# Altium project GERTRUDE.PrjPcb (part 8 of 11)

## Sheet HEADERS_JMEDIA_JMISC.SchDoc: JMEDIA JMISC
size A3; SheetNumber: 21; SheetTotal: 51
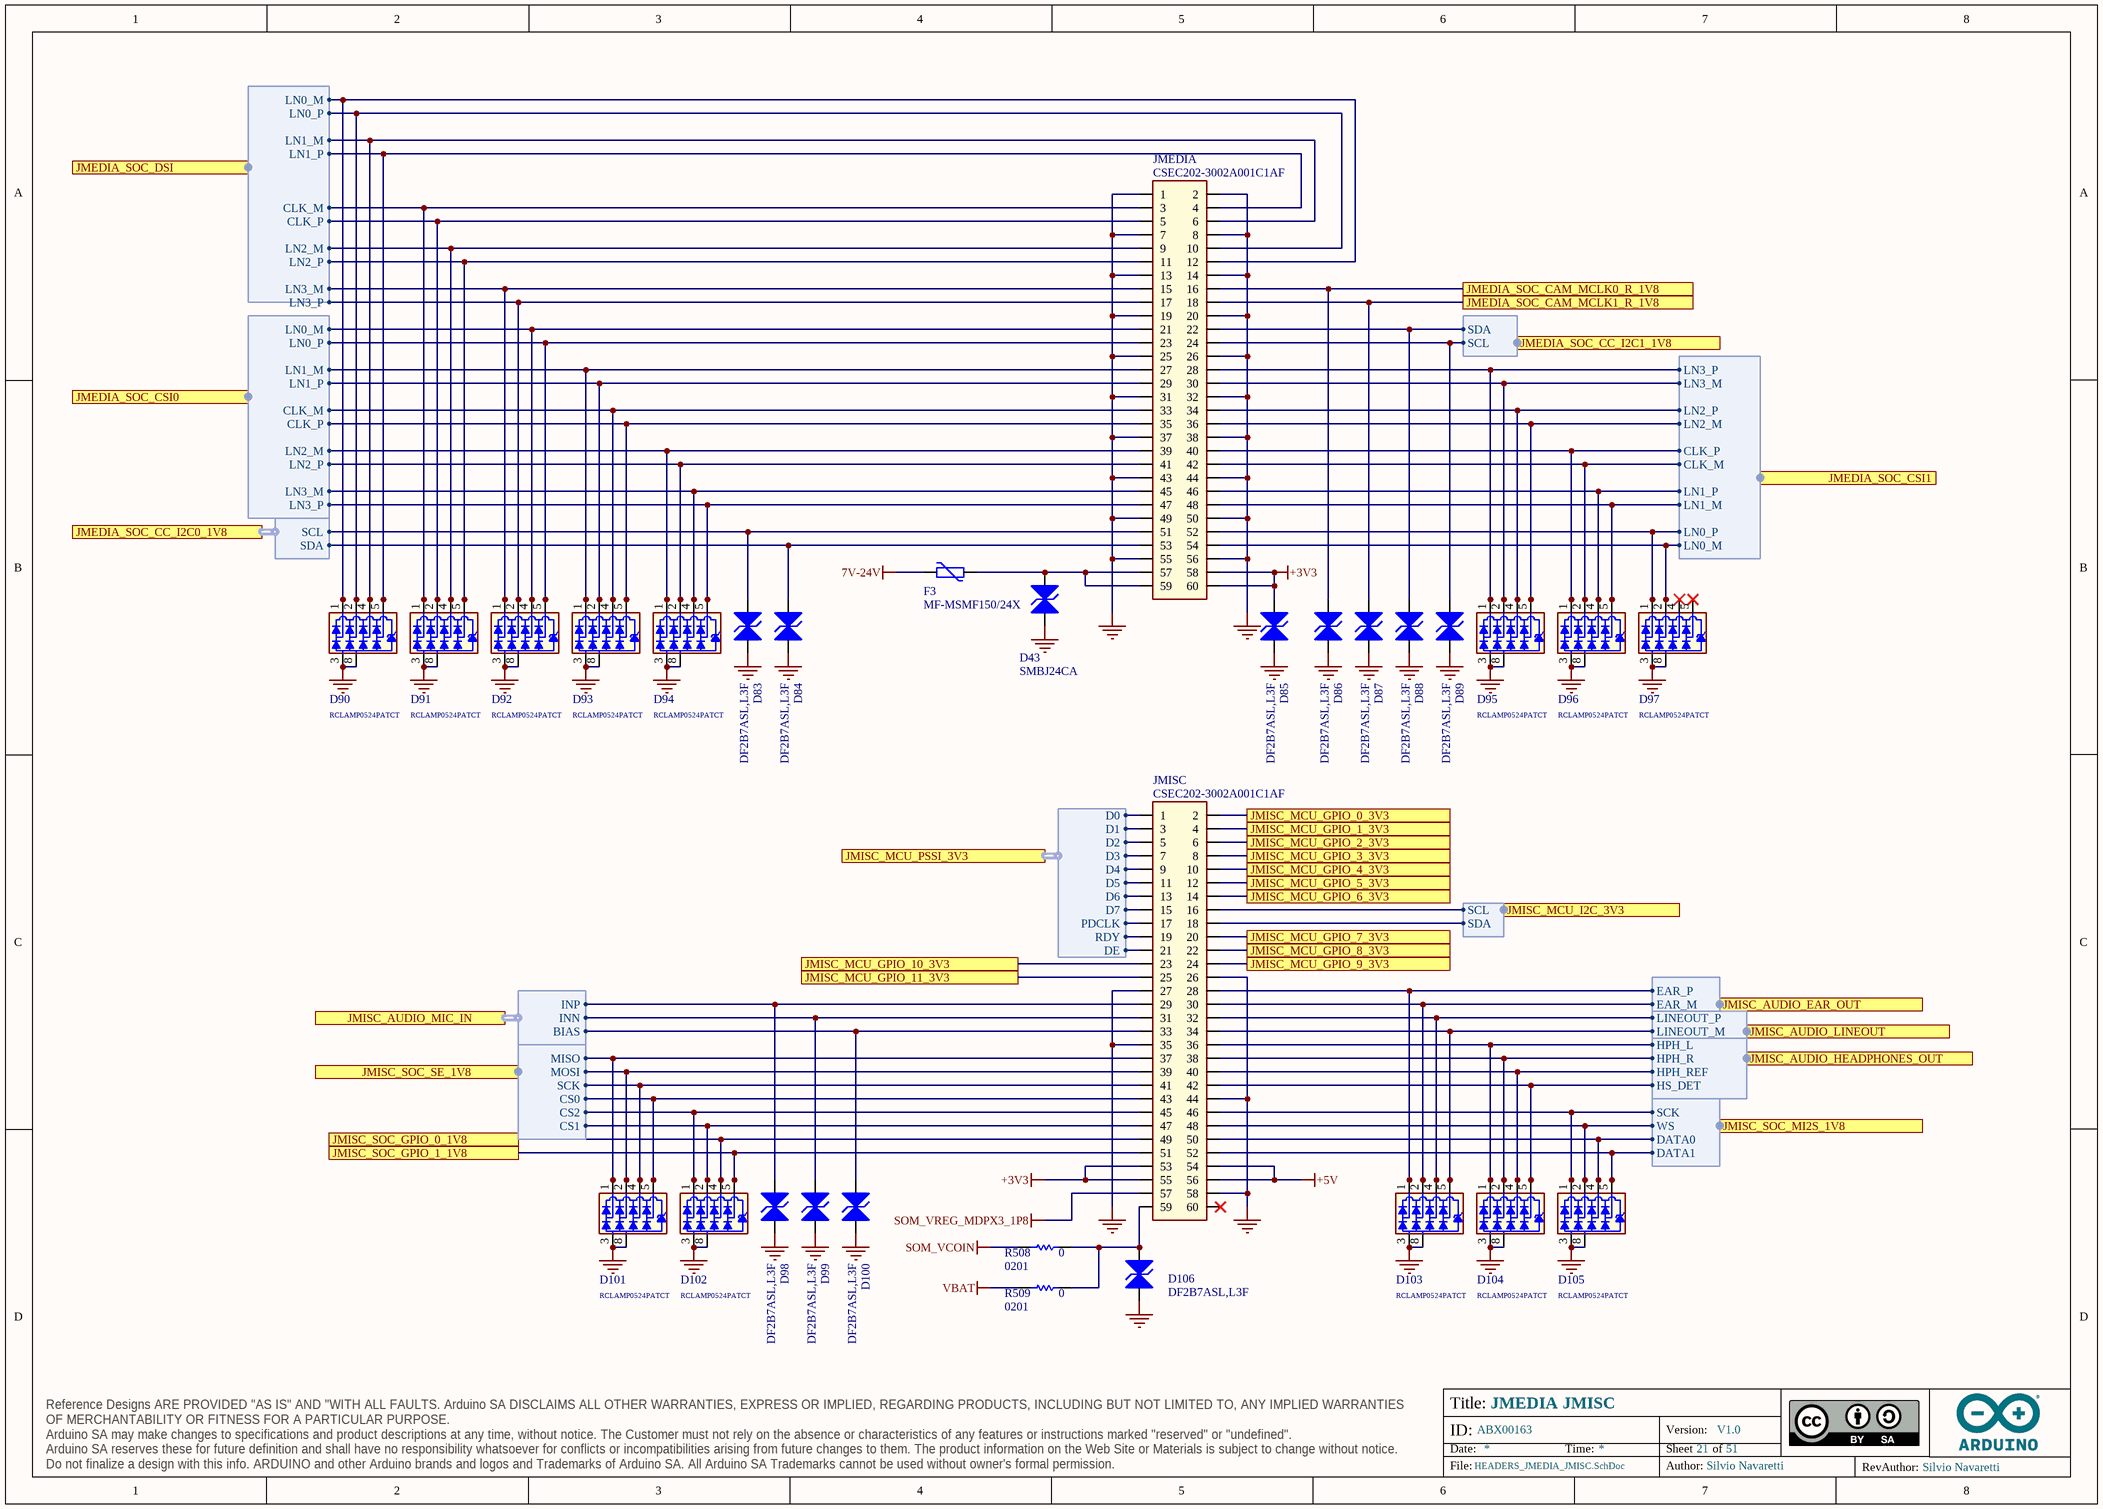
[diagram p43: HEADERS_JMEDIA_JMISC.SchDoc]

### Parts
D43  SMBJ24CA  [SMB_NOPOLARITY]
D83  DF2B7ASL,L3F  [DF2B7ASL,L3F]
D84  DF2B7ASL,L3F  [DF2B7ASL,L3F]
D85  DF2B7ASL,L3F  [DF2B7ASL,L3F]
D86  DF2B7ASL,L3F  [DF2B7ASL,L3F]
D87  DF2B7ASL,L3F  [DF2B7ASL,L3F]
D88  DF2B7ASL,L3F  [DF2B7ASL,L3F]
D89  DF2B7ASL,L3F  [DF2B7ASL,L3F]
D90  RCLAMP0524PATCT  [SLP2510P8]
D91  RCLAMP0524PATCT  [SLP2510P8]
D92  RCLAMP0524PATCT  [SLP2510P8]
D93  RCLAMP0524PATCT  [SLP2510P8]
D94  RCLAMP0524PATCT  [SLP2510P8]
D95  RCLAMP0524PATCT  [SLP2510P8]
D96  RCLAMP0524PATCT  [SLP2510P8]
D97  RCLAMP0524PATCT  [SLP2510P8]
D98  DF2B7ASL,L3F  [DF2B7ASL,L3F]
D99  DF2B7ASL,L3F  [DF2B7ASL,L3F]
D100  DF2B7ASL,L3F  [DF2B7ASL,L3F]
D101  RCLAMP0524PATCT  [SLP2510P8]
D102  RCLAMP0524PATCT  [SLP2510P8]
D103  RCLAMP0524PATCT  [SLP2510P8]
D104  RCLAMP0524PATCT  [SLP2510P8]
D105  RCLAMP0524PATCT  [SLP2510P8]
D106  DF2B7ASL,L3F  [DF2B7ASL,L3F]
F3  MF-MSMF150/24X  [1812]
JMEDIA  CSEC202-3002A001C1AF  [CSEC202-3002A001C1AF]
JMISC  CSEC202-3002A001C1AF  [CSEC202-3002A001C1AF]
R508  value 0  Case Code (Imperial): 0201  [RES-0201]  (hidden comment: CRCW02010000Z0ED)
R509  value 0  Case Code (Imperial): 0201  [RES-0201]  (hidden comment: CRCW02010000Z0ED)

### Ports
JMEDIA_SOC_CAM_MCLK0_R_1V8, JMEDIA_SOC_CAM_MCLK1_R_1V8, JMEDIA_SOC_CC_I2C0_1V8 (harness I2C), JMEDIA_SOC_CC_I2C1_1V8 (harness I2C), JMEDIA_SOC_CSI0 (harness MIPI_4LANES), JMEDIA_SOC_CSI1 (harness MIPI_4LANES), JMEDIA_SOC_DSI (harness MIPI_4LANES), JMISC_AUDIO_EAR_OUT (harness EAT), JMISC_AUDIO_HEADPHONES_OUT (harness HEADPHONES), JMISC_AUDIO_LINEOUT (harness LINEOUT), JMISC_AUDIO_MIC_IN (harness MIC), JMISC_MCU_GPIO_0_3V3, JMISC_MCU_GPIO_1_3V3, JMISC_MCU_GPIO_2_3V3, JMISC_MCU_GPIO_3_3V3, JMISC_MCU_GPIO_4_3V3, JMISC_MCU_GPIO_5_3V3, JMISC_MCU_GPIO_6_3V3, JMISC_MCU_GPIO_7_3V3, JMISC_MCU_GPIO_8_3V3, JMISC_MCU_GPIO_9_3V3, JMISC_MCU_GPIO_10_3V3, JMISC_MCU_GPIO_11_3V3, JMISC_MCU_I2C_3V3 (harness I2C), JMISC_MCU_PSSI_3V3 (harness PSSI), JMISC_SOC_GPIO_0_1V8, JMISC_SOC_GPIO_1_1V8, JMISC_SOC_MI2S_1V8 (harness SOM_MD_I2S), JMISC_SOC_SE_1V8 (harness SOM_MD_SPI_3CS)

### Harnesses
MIPI_4LANES: LN3_M, LN2_M, LN2_P, LN0_M, LN0_P, CLK_M, CLK_P, LN1_M, LN1_P, LN3_P
I2C: SDA, SCL
EAT: EAR_P, EAR_M
MIC: INP, INN, BIAS
LINEOUT: LINEOUT_P, LINEOUT_M
HEADPHONES: HPH_L, HPH_R, HPH_REF, HS_DET
SOM_MD_SPI_3CS: SCK, MISO, MOSI, CS0, CS1, CS2
SOM_MD_I2S: SCK, WS, DATA0, DATA1
PSSI: D0, D1, D2, D3, D4, D5, D6, D7, PDCLK, RDY, DE

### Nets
7V-24V: F3.1
+3V3: D85.2(A2) JMEDIA.58 JMEDIA.60 JMISC.53 JMISC.55
+5V: JMISC.54 JMISC.56
GND: D43.1(A1) D83.1(A1) D84.1(A1) D85.1(A1) D86.1(A1) D87.1(A1) D88.1(A1) D89.1(A1) D90.3 D90.8 D91.3 D91.8 D92.3 D92.8 D93.3 D93.8 D94.3 D94.8 D95.3 D95.8 D96.3 D96.8 D97.3 D97.8 D98.1(A1) D99.1(A1) D100.1(A1) D101.3 D101.8 D102.3 D102.8 D103.3 D103.8 D104.3 D104.8 D105.3 D105.8 D106.1(A1) JMEDIA.1 JMEDIA.2 JMEDIA.7 JMEDIA.8 JMEDIA.13 JMEDIA.14 JMEDIA.19 JMEDIA.20 JMEDIA.25 JMEDIA.26 JMEDIA.31 JMEDIA.32 JMEDIA.37 JMEDIA.38 JMEDIA.43 JMEDIA.44 JMEDIA.49 JMEDIA.50 JMEDIA.55 JMEDIA.56 JMISC.26 JMISC.27 JMISC.35 JMISC.44 JMISC.58
SOM_VCOIN: R508.2
SOM_VREG_MDPX3_1P8: JMISC.57
VBAT: R509.2
A_CLK_N: D91.1 D91.10 JMEDIA.3 ; port JMEDIA_SOC_DSI.CLK_M
A_CLK_N: D93.4 D93.7 JMEDIA.33 ; port JMEDIA_SOC_CSI0.CLK_M  [a separate net that carries the same name]
A_CLK_N: D96.2 D96.9 JMEDIA.42 ; port JMEDIA_SOC_CSI1.CLK_M  [a separate net that carries the same name]
A_CLK_P: D91.2 D91.9 JMEDIA.5 ; port JMEDIA_SOC_DSI.CLK_P
A_CLK_P: D93.5 D93.6 JMEDIA.35 ; port JMEDIA_SOC_CSI0.CLK_P  [a separate net that carries the same name]
A_CLK_P: D96.1 D96.10 JMEDIA.40 ; port JMEDIA_SOC_CSI1.CLK_P  [a separate net that carries the same name]
A_LN0_N: D90.1 D90.10 JMEDIA.12 ; port JMEDIA_SOC_DSI.LN0_M
A_LN0_N: D92.4 D92.7 JMEDIA.21 ; port JMEDIA_SOC_CSI0.LN0_M  [a separate net that carries the same name]
A_LN0_N: D97.2 D97.9 JMEDIA.54 ; port JMEDIA_SOC_CSI1.LN0_M  [a separate net that carries the same name]
A_LN0_P: D90.2 D90.9 JMEDIA.10 ; port JMEDIA_SOC_DSI.LN0_P
A_LN0_P: D92.5 D92.6 JMEDIA.23 ; port JMEDIA_SOC_CSI0.LN0_P  [a separate net that carries the same name]
A_LN0_P: D97.1 D97.10 JMEDIA.52 ; port JMEDIA_SOC_CSI1.LN0_P  [a separate net that carries the same name]
A_LN1_N: D90.4 D90.7 JMEDIA.6 ; port JMEDIA_SOC_DSI.LN1_M
A_LN1_N: D93.1 D93.10 JMEDIA.27 ; port JMEDIA_SOC_CSI0.LN1_M  [a separate net that carries the same name]
A_LN1_N: D96.5 D96.6 JMEDIA.48 ; port JMEDIA_SOC_CSI1.LN1_M  [a separate net that carries the same name]
A_LN1_P: D90.5 D90.6 JMEDIA.4 ; port JMEDIA_SOC_DSI.LN1_P
A_LN1_P: D93.2 D93.9 JMEDIA.29 ; port JMEDIA_SOC_CSI0.LN1_P  [a separate net that carries the same name]
A_LN1_P: D96.4 D96.7 JMEDIA.46 ; port JMEDIA_SOC_CSI1.LN1_P  [a separate net that carries the same name]
A_LN2_N: D91.4 D91.7 JMEDIA.9 ; port JMEDIA_SOC_DSI.LN2_M
A_LN2_N: D94.1 D94.10 JMEDIA.39 ; port JMEDIA_SOC_CSI0.LN2_M  [a separate net that carries the same name]
A_LN2_N: D95.5 D95.6 JMEDIA.36 ; port JMEDIA_SOC_CSI1.LN2_M  [a separate net that carries the same name]
A_LN2_P: D91.5 D91.6 JMEDIA.11 ; port JMEDIA_SOC_DSI.LN2_P
A_LN2_P: D94.2 D94.9 JMEDIA.41 ; port JMEDIA_SOC_CSI0.LN2_P  [a separate net that carries the same name]
A_LN2_P: D95.4 D95.7 JMEDIA.34 ; port JMEDIA_SOC_CSI1.LN2_P  [a separate net that carries the same name]
A_LN3_N: D92.1 D92.10 JMEDIA.15 ; port JMEDIA_SOC_DSI.LN3_M
A_LN3_N: D94.4 D94.7 JMEDIA.45 ; port JMEDIA_SOC_CSI0.LN3_M  [a separate net that carries the same name]
A_LN3_N: D95.2 D95.9 JMEDIA.30 ; port JMEDIA_SOC_CSI1.LN3_M  [a separate net that carries the same name]
A_LN3_P: D92.2 D92.9 JMEDIA.17 ; port JMEDIA_SOC_DSI.LN3_P
A_LN3_P: D94.5 D94.6 JMEDIA.47 ; port JMEDIA_SOC_CSI0.LN3_P  [a separate net that carries the same name]
A_LN3_P: D95.1 D95.10 JMEDIA.28 ; port JMEDIA_SOC_CSI1.LN3_P  [a separate net that carries the same name]
MD_CCI_I2C0.SCL: D83.2(A2) JMEDIA.51 ; port JMEDIA_SOC_CC_I2C0_1V8.SCL
MD_CCI_I2C0.SDA: D84.2(A2) JMEDIA.53 ; port JMEDIA_SOC_CC_I2C0_1V8.SDA
MD_CCI_I2C2.SCL: D89.2(A2) JMEDIA.24 ; port JMEDIA_SOC_CC_I2C1_1V8.SCL
MD_CCI_I2C2.SDA: D88.2(A2) JMEDIA.22 ; port JMEDIA_SOC_CC_I2C1_1V8.SDA
MD_GPIO_10: D101.1 D101.10 JMISC.37 ; port JMISC_SOC_SE_1V8.MISO
MD_GPIO_11: D101.2 D101.9 JMISC.39 ; port JMISC_SOC_SE_1V8.MOSI
MD_GPIO_12: D101.4 D101.7 JMISC.41 ; port JMISC_SOC_SE_1V8.SCK
MD_GPIO_13: D101.5 D101.6 JMISC.43 ; port JMISC_SOC_SE_1V8.CS0
MD_GPIO_14: D102.2 D102.9 JMISC.47 ; port JMISC_SOC_SE_1V8.CS1
MD_GPIO_15: D102.1 D102.10 JMISC.45 ; port JMISC_SOC_SE_1V8.CS2
MD_GPIO_67: D86.2(A2) JMEDIA.16 ; port JMEDIA_SOC_CAM_MCLK0_R_1V8
MD_GPIO_68: D87.2(A2) JMEDIA.18 ; port JMEDIA_SOC_CAM_MCLK1_R_1V8
MD_GPIO_73: D102.4 D102.7 JMISC.49 ; port JMISC_SOC_GPIO_0_1V8
MD_GPIO_74: D102.5 D102.6 JMISC.51 ; port JMISC_SOC_GPIO_1_1V8
MD_LPASS_GPIO_120: D105.1 D105.10 JMISC.46 ; port JMISC_SOC_MI2S_1V8.SCK
MD_LPASS_GPIO_121: D105.2 D105.9 JMISC.48 ; port JMISC_SOC_MI2S_1V8.WS
MD_LPASS_GPIO_122: D105.4 D105.7 JMISC.50 ; port JMISC_SOC_MI2S_1V8.DATA0
MD_LPASS_GPIO_123: D105.5 D105.6 JMISC.52 ; port JMISC_SOC_MI2S_1V8.DATA1
MIC_IN5_IN6.BIAS: D100.2(A2) JMISC.33 ; port JMISC_AUDIO_MIC_IN.BIAS
PA0: JMISC.20 ; port JMISC_MCU_GPIO_7_3V3
PA1: JMISC.22 ; port JMISC_MCU_GPIO_8_3V3
PA2: JMISC.24 ; port JMISC_MCU_GPIO_9_3V3
PA6: JMISC.17 ; port JMISC_MCU_PSSI_3V3.PDCLK
PA9: JMISC.1 ; port JMISC_MCU_PSSI_3V3.D0
PA11: JMISC.23 ; port JMISC_MCU_GPIO_10_3V3
PA12: JMISC.25 ; port JMISC_MCU_GPIO_11_3V3
PC7: JMISC.3 ; port JMISC_MCU_PSSI_3V3.D1
PC8: JMISC.5 ; port JMISC_MCU_PSSI_3V3.D2
PC11: JMISC.9 ; port JMISC_MCU_PSSI_3V3.D4
PD3: JMISC.11 ; port JMISC_MCU_PSSI_3V3.D5
PE1: JMISC.7 ; port JMISC_MCU_PSSI_3V3.D3
PE2: JMISC.2 ; port JMISC_MCU_GPIO_0_3V3
PE3: JMISC.4 ; port JMISC_MCU_GPIO_1_3V3
PE4: JMISC.6 ; port JMISC_MCU_GPIO_2_3V3
PE5: JMISC.8 ; port JMISC_MCU_GPIO_3_3V3
PE6: JMISC.10 ; port JMISC_MCU_GPIO_4_3V3
PE7: JMISC.12 ; port JMISC_MCU_GPIO_5_3V3
PE8: JMISC.14 ; port JMISC_MCU_GPIO_6_3V3
PF0: JMISC.18 ; port JMISC_MCU_I2C_3V3.SDA
PF1: JMISC.16 ; port JMISC_MCU_I2C_3V3.SCL
PF4: JMISC.13 ; port JMISC_MCU_PSSI_3V3.D6
PH8: JMISC.21 ; port JMISC_MCU_PSSI_3V3.DE
PI5: JMISC.19 ; port JMISC_MCU_PSSI_3V3.RDY
PI7: JMISC.15 ; port JMISC_MCU_PSSI_3V3.D7
NetC209_2: D98.2(A2) JMISC.29 ; port JMISC_AUDIO_MIC_IN.INP
NetC217_2: D99.2(A2) JMISC.31 ; port JMISC_AUDIO_MIC_IN.INN
NetC248_2: D104.1 D104.10 JMISC.36 ; port JMISC_AUDIO_HEADPHONES_OUT.HPH_L
NetC295_2: D104.2 D104.9 JMISC.38 ; port JMISC_AUDIO_HEADPHONES_OUT.HPH_R
NetD43_2: D43.2(A2) F3.2 JMEDIA.57 JMEDIA.59
NetD97_4: D97.4 D97.7
NetD97_5: D97.5 D97.6
NetD103_1: D103.1 D103.10 JMISC.28 ; port JMISC_AUDIO_EAR_OUT.EAR_P
NetD103_2: D103.2 D103.9 JMISC.30 ; port JMISC_AUDIO_EAR_OUT.EAR_M
NetD103_4: D103.4 D103.7 JMISC.32 ; port JMISC_AUDIO_LINEOUT.LINEOUT_P
NetD103_5: D103.5 D103.6 JMISC.34 ; port JMISC_AUDIO_LINEOUT.LINEOUT_M
NetD104_4: D104.4 D104.7 JMISC.40 ; port JMISC_AUDIO_HEADPHONES_OUT.HPH_REF
NetD104_5: D104.5 D104.6 JMISC.42 ; port JMISC_AUDIO_HEADPHONES_OUT.HS_DET
NetD106_2: D106.2(A2) JMISC.59 R508.1 R509.1

Not connected (* = marked no-connect by the designer): JMISC 60*

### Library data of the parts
D43 = D0070-A.2: TVS BIDIRECTIONAL SMD Vr 24V, Vbr min 26.7V, 600W, SMB; Manufacturer: Littlefuse; V(BR) Typ (V): 26.7; Code Arduino: D0070
D83-D89 D98-D100 D106 = D0099-5: TVS BIDIRECTIONAL SMD Vr 5.5V, Vbr min 5.8V, 0.62x0.32mm; Manufacturer: TOSHIBA; Vforward max: 0V; Ireverse max: 1µA; Power max: 80W; Code Arduino: D0099; Vreverse max: 20V
D90-D97 D101-D105 = D0097-A.6: TVS UNIDIRECTIONAL 4CH 0.8pF 5V SLP2510P8 10-pin 2.5x1.0x0.58mm; Manufacturer: SEMTECH; Code Arduino: D0097; Device Type: ESD protection
F3 = P0019-A.1: PTC Ihold 1.5A Itrip 3A 24V 1812; Manufacturer: Bourns; Code Arduino: P0019
JMEDIA JMISC = J0565-A.3: CONN HEADER FEMALE VERTICAL SMD 1.27mm 2x30 POS heigth 4.4mm; Manufacturer: Greenconn; Code Arduino: J0565
R508 R509 = R0140-A.21: RES CHIP 0201 0R; Manufacturer: Vishay; Temperature coefficient: 0ppm; Code Arduino: R0140; Power: 50mW; Tolerance: 0%

## Sheet HEADERS_JCTL.SchDoc: JCTL
size A3; SheetNumber: 23; SheetTotal: 51
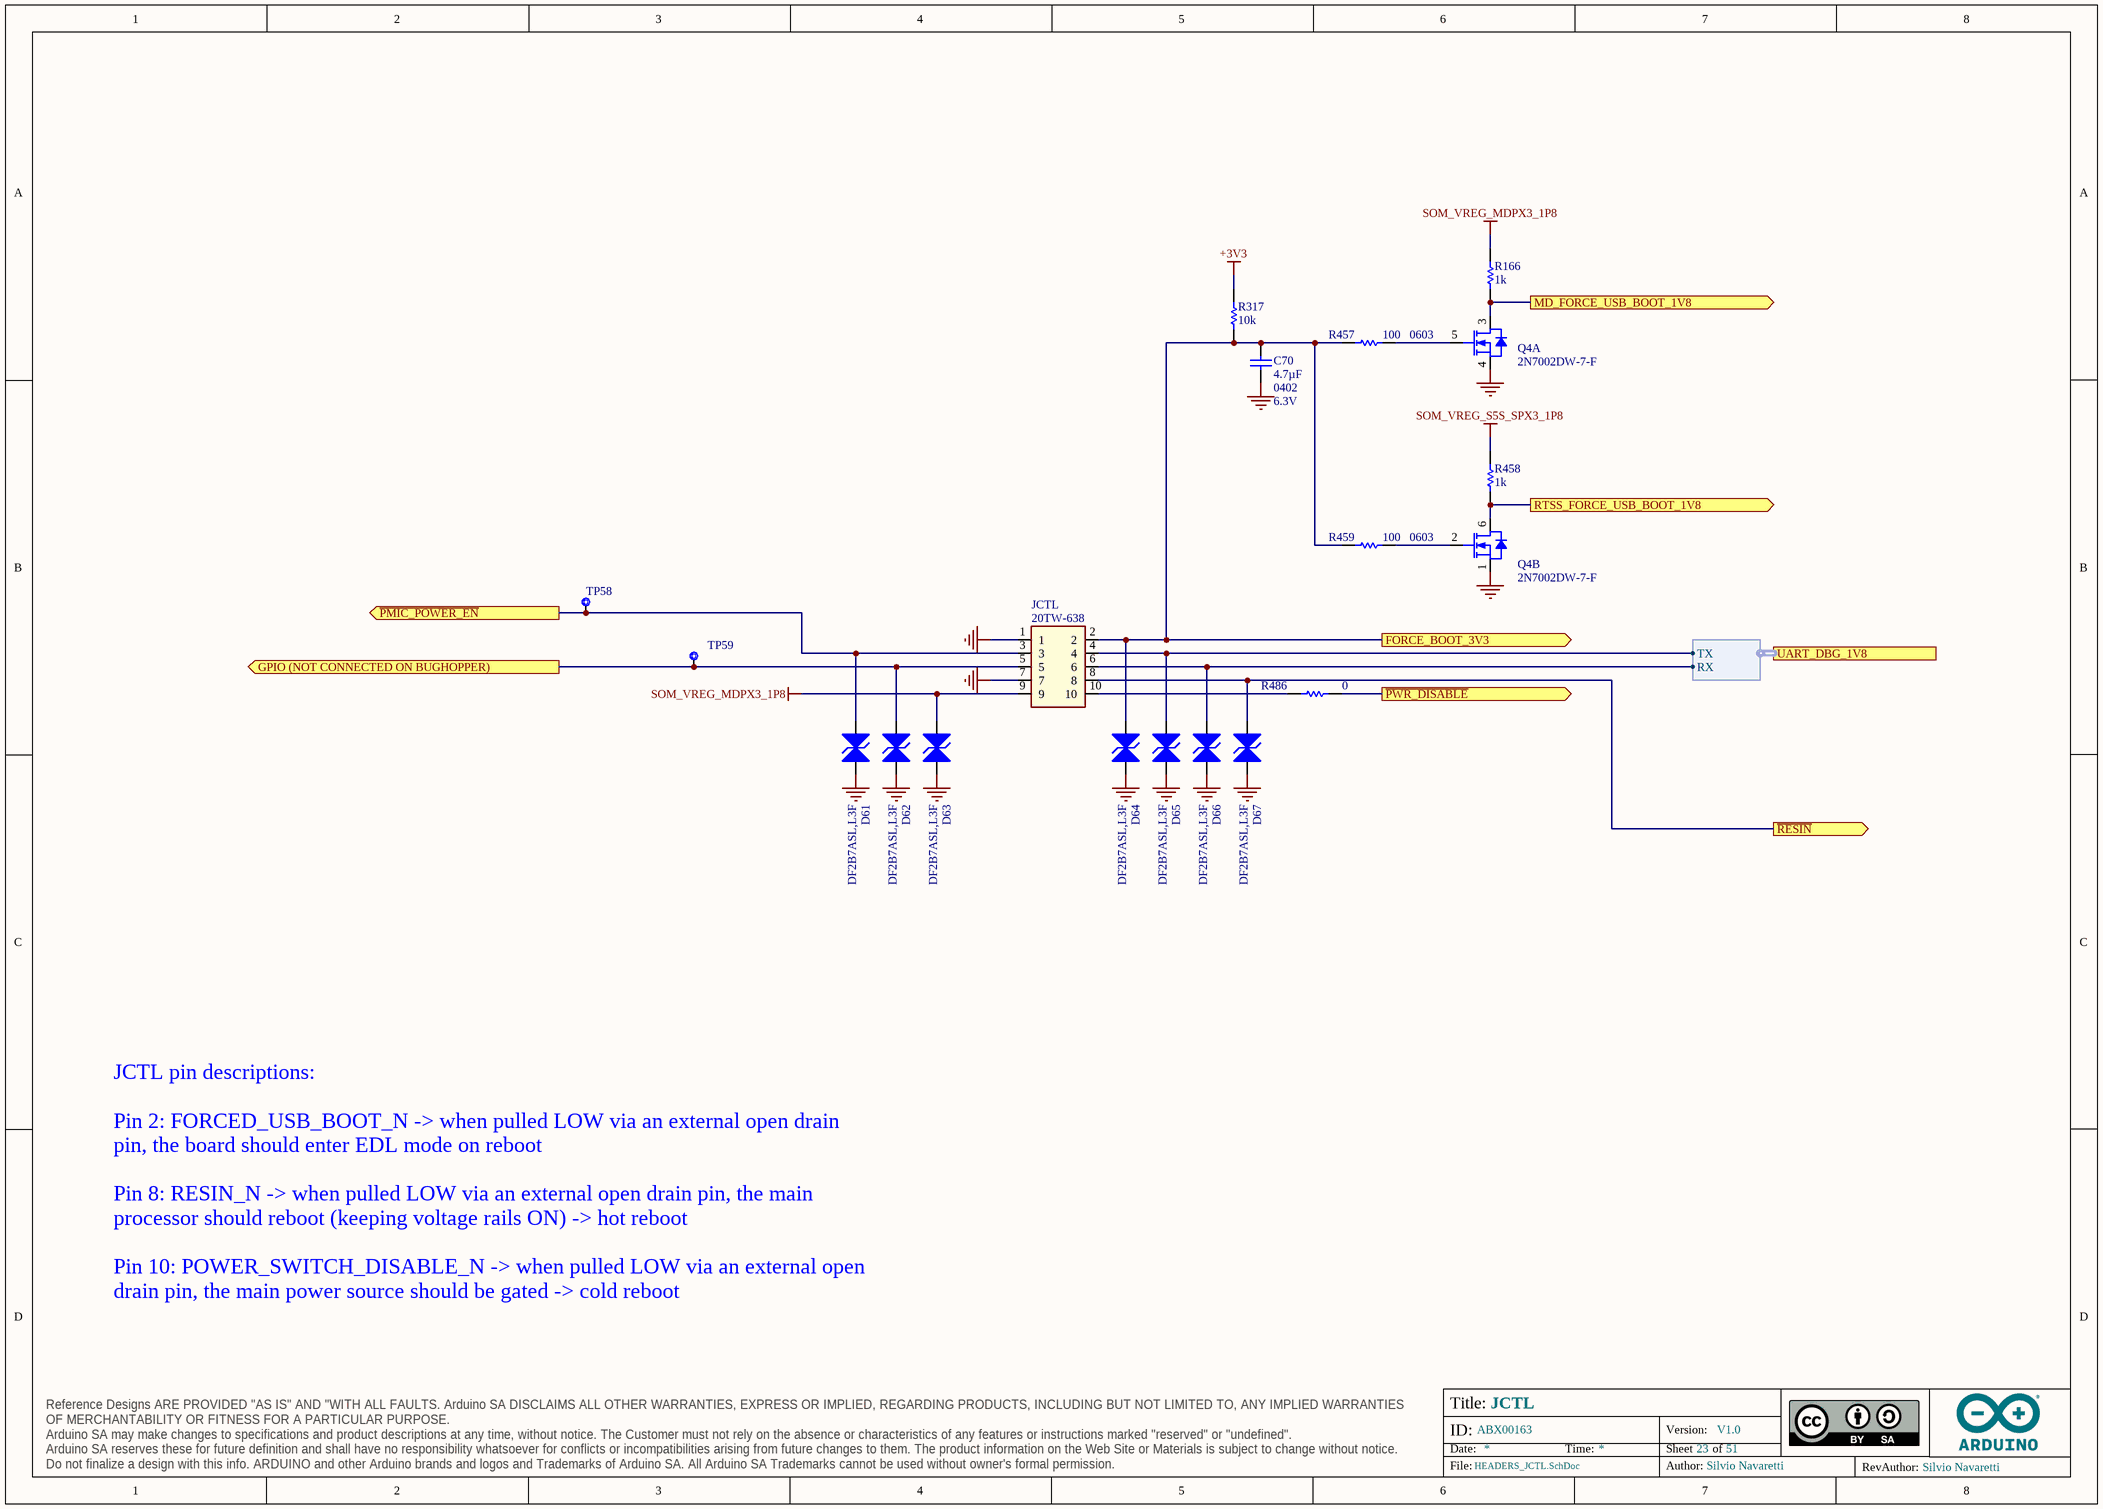
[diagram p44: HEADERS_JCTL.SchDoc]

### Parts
C70  value 4.7µF  Case Code (Imperial): 0402  Voltage: 6.3V  [CAP-0402]  (hidden comment: C1005A475M6R3NT)
D61  DF2B7ASL,L3F  [DF2B7ASL,L3F]
D62  DF2B7ASL,L3F  [DF2B7ASL,L3F]
D63  DF2B7ASL,L3F  [DF2B7ASL,L3F]
D64  DF2B7ASL,L3F  [DF2B7ASL,L3F]
D65  DF2B7ASL,L3F  [DF2B7ASL,L3F]
D66  DF2B7ASL,L3F  [DF2B7ASL,L3F]
D67  DF2B7ASL,L3F  [DF2B7ASL,L3F]
JCTL  20TW-638  [20TW-638]
Q4  2N7002DW-7-F  [SOT363]  (parts A,B of 2)
R166  value 1k  [RES-0201]  (hidden comment: RC0201FR-071KL)
R317  value 10k  [RES-0201]  (hidden comment: RC0201FR-0710KL)
R457  value 100  Case Code (Imperial): 0603  [RES-0603]  (hidden comment: CRCW0603100RFKEAC)
R458  value 1k  [RES-0201]  (hidden comment: RC0201FR-071KL)
R459  value 100  Case Code (Imperial): 0603  [RES-0603]  (hidden comment: CRCW0603100RFKEAC)
R486  value 0  [RES-0201]  (hidden comment: CRCW02010000Z0ED)
TP58  Test point 1.00mm  [TP-1.00MM]  (value not drawn)  (no BOM)
TP59  Test point 1.00mm  [TP-1.00MM]  (value not drawn)  (no BOM)

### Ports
FORCE_BOOT_3V3 (out), GPIO (NOT CONNECTED ON BUGHOPPER) (out), MD_FORCE_USB_BOOT_1V8 (out), RTSS_FORCE_USB_BOOT_1V8 (out), UART_DBG_1V8 (harness UART), ~{PMIC_POWER_EN} (out), ~{PWR_DISABLE} (out), ~{RESIN} (out)

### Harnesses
UART: TX, RX

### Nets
+3V3: R317.2
GND: C70.2 D61.1(A1) D62.1(A1) D63.1(A1) D64.1(A1) D65.1(A1) D66.1(A1) D67.1(A1) JCTL.1 JCTL.7 Q4.1(S) Q4.4(S)
SOM_VREG_MDPX3_1P8: D63.2(A2) JCTL.9 R166.1
SOM_VREG_S5S_SPX3_1P8: R458.1
FORCE_BOOT_3V3: C70.1 D64.2(A2) JCTL.2 R317.1 R457.2 R459.2 ; port FORCE_BOOT_3V3
MD_GPIO_43: D65.2(A2) JCTL.4 ; port UART_DBG_1V8.TX
MD_GPIO_44: D66.2(A2) JCTL.6 ; port UART_DBG_1V8.RX
~{PM_RESIN_N_3V3}: D67.2(A2) JCTL.8 ; port ~{RESIN}
~{POWER_DISABLE_7-24V}: R486.1 ; port ~{PWR_DISABLE}
NetD61_2: D61.2(A2) JCTL.3 TP58.X ; port ~{PMIC_POWER_EN}
NetD62_2: D62.2(A2) JCTL.5 TP59.X ; port GPIO (NOT CONNECTED ON BUGHOPPER)
NetJCTL_10: JCTL.10 R486.2
NetQ4_2: Q4.2(G) R459.1
NetQ4_3: Q4.3(D) R166.2 ; port MD_FORCE_USB_BOOT_1V8
NetQ4_5: Q4.5(G) R457.1
NetQ4_6: Q4.6(D) R458.2 ; port RTSS_FORCE_USB_BOOT_1V8

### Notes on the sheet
- JCTL pin descriptions:
  Pin 2: FORCED_USB_BOOT_N -> when pulled LOW via an external open drain pin, the board should enter EDL mode on reboot
  Pin 8: RESIN_N -> when pulled LOW via an external open drain pin, the main processor should reboot (keeping voltage rails ON) -> hot reboot
  Pin 10: POWER_SWITCH_DISABLE_N -> when pulled LOW via an external open drain pin, the main power source should be gated -> cold reboot

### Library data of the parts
C70 = C0037-A.14: CAP CHIP 0402 4.7uF 20% 6V3 X5R; Manufacturer: Hottech; Code Arduino: 0833
D61-D67 = D0099-5: as D83-D89 on sheet HEADERS_JMEDIA_JMISC
JCTL = J0570-A.1: CONN HEADER MALE 10POS 2x5 2.54mm SMD; Manufacturer: 4UCONN; Number of Contacts: 10; Connector Type: BOARD CONNECTOR; Code Arduino: J0570
Q4 = T0011-A.12: MOSFET 2N-CH 60V 0.32A SOT363; Manufacturer: Diodes Inc.; Device Type: Mosfet 2N-CH SMD; Code Arduino: A5500
R166 R458 = R0195-A.22: RES CHIP 0201 1k 1% 1/20W; Manufacturer: Yageo; Power: 50mW; Temperature coefficient: 200ppm; Code Arduino: R0195
R317 = R0145-A.21: RES CHIP 0201 10k 1% 1/20W; Manufacturer: Yageo; Power: 50mW; Temperature coefficient: 200ppm; Code Arduino: R0145
R457 R459 = R0105-A.22: RES CHIP 0603 100R 1% 1/10W; Manufacturer: Vishay; Power: 100mW; Temperature coefficient: 100ppm; Code Arduino: A5099
R486 = R0140-A.21: as R508 on sheet HEADERS_JMEDIA_JMISC
TP58 TP59 = UT0013-A.6: Part Number: This is not a component

## Sheet HEATSINK_FAN.SchDoc: HEATSINK FAN
size A3; SheetNumber: 50; SheetTotal: 51
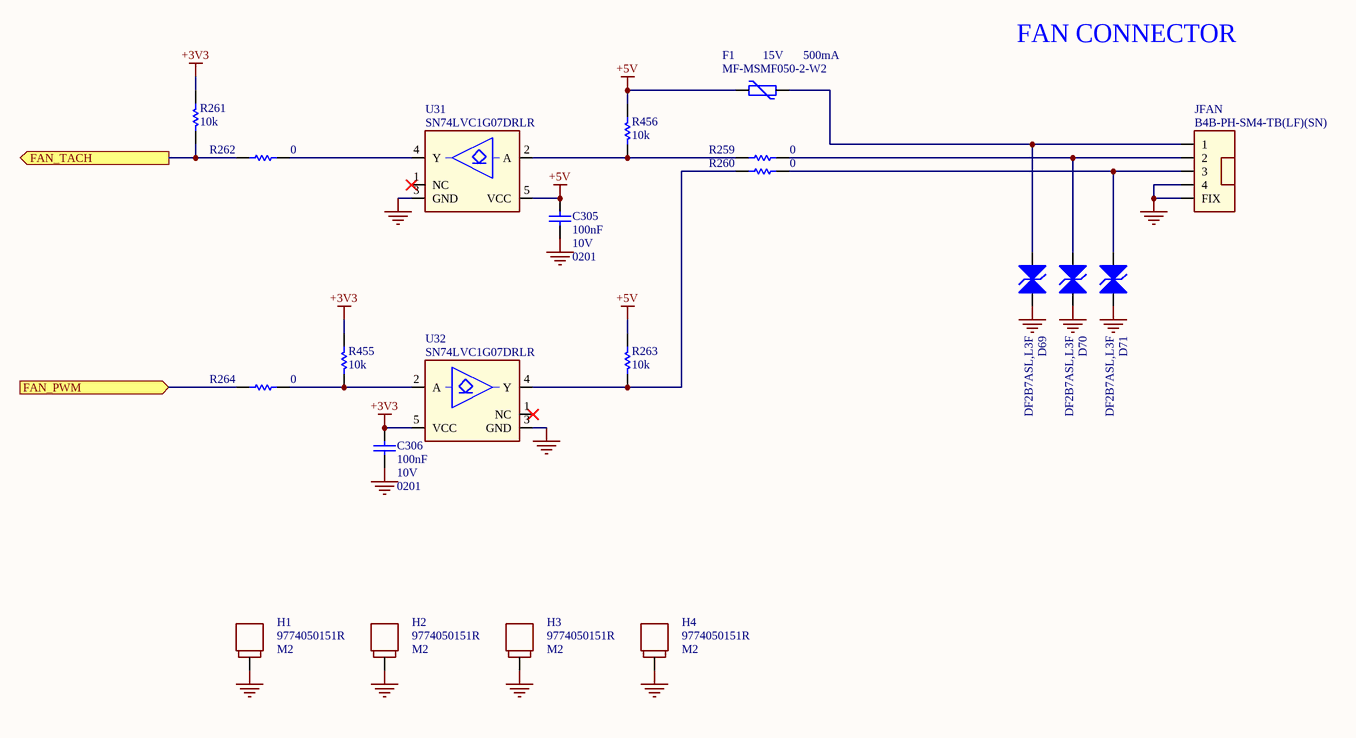
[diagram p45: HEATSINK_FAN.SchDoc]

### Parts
C305  value 100nF  Voltage: 10V  Case Code (Imperial): 0201  [CAP-0201]  (hidden comment: CL03A104KP3NNNC)
C306  value 100nF  Voltage: 10V  Case Code (Imperial): 0201  [CAP-0201]  (hidden comment: CL03A104KP3NNNC)
D69  DF2B7ASL,L3F  [DF2B7ASL,L3F]
D70  DF2B7ASL,L3F  [DF2B7ASL,L3F]
D71  DF2B7ASL,L3F  [DF2B7ASL,L3F]
F1  MF-MSMF050-2-W2  Hold Current: 500mA  Operating Supply Voltage: 15V  [1812]
H1  9774050151R  [9774050151R]
H2  9774050151R  [9774050151R]
H3  9774050151R  [9774050151R]
H4  9774050151R  [9774050151R]
JFAN  B4B-PH-SM4-TB(LF)(SN)  [B4B-PH-SM4-TB(LF)(SN)]
R259  value 0  [RES-0201]  (hidden comment: CRCW02010000Z0ED)
R260  value 0  [RES-0201]  (hidden comment: CRCW02010000Z0ED)
R261  value 10k  [RES-0201]  (hidden comment: RC0201FR-0710KL)
R262  value 0  [RES-0201]  (hidden comment: CRCW02010000Z0ED)
R263  value 10k  [RES-0201]  (hidden comment: RC0201FR-0710KL)
R264  value 0  [RES-0201]  (hidden comment: CRCW02010000Z0ED)
R455  value 10k  [RES-0201]  (hidden comment: RC0201FR-0710KL)
R456  value 10k  [RES-0201]  (hidden comment: RC0201FR-0710KL)
U31  SN74LVC1G07DRLR  [TI DRL DRL0005A]
U32  SN74LVC1G07DRLR  [TI DRL DRL0005A]

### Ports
FAN_PWM (in), FAN_TACH (out)

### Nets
+3V3: C306.2 R261.2 R455.2 U32.5(VCC)
+5V: C305.2 F1.1 R263.2 R456.2 U31.5(VCC)
GND: C305.1 C306.1 D69.1(A1) D70.1(A1) D71.1(A1) H1.1 H2.1 H3.1 H4.1 JFAN.4 JFAN.FIX U31.3(GND) U32.3(GND)
PA7: R261.1 R262.2 ; port FAN_TACH
PG15: R264.2 ; port FAN_PWM
NetD69_2: D69.2(A2) F1.2 JFAN.1
NetD70_2: D70.2(A2) JFAN.2 R259.1
NetD71_2: D71.2(A2) JFAN.3 R260.1
NetR259_2: R259.2 R456.1 U31.2(A)
NetR260_2: R260.2 R263.1 U32.4(Y)
NetR262_1: R262.1 U31.4(Y)
NetR264_1: R264.1 R455.1 U32.2(A)

Not connected (* = marked no-connect by the designer): U31 1(NC)*; U32 1(NC)*

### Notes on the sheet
- FAN CONNECTOR

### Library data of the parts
C305 C306 = C0113-A.6: CAP CHIP 0201 100nF 10% 10V X5R; Manufacturer: Samsung Electro-Mechanics; Code Arduino: C0113
D69-D71 = D0099-5: as D83-D89 on sheet HEADERS_JMEDIA_JMISC
F1 = P0002-A.7: PTC RESET FUSE 15V 500MA 1812 LOGO OO ARDUINO; Manufacturer: Bourns; Approvals: UL,CSA,TUV; Time to Trip: 0.15s; Max Current Rating: 100A; Trip Current: 1A; Resistance: 150mR; Code Arduino: 3335; Power Dissipation: 800mW
H1-H4 = S0005-A.6: M2.5 SPACER SMT ROUND STEEL H=5mm; Manufacturer: Würth Elektronik; Code Arduino: S0005
JFAN = J0557-A.2: CONN Header SMD 1x4 vertical polarized; Manufacturer: JST; Code Arduino: J0557
R259 R260 R262 R264 = R0140-A.21: as R508 on sheet HEADERS_JMEDIA_JMISC
R261 R263 R455 R456 = R0145-A.21: as R317 on sheet HEADERS_JCTL
U31 U32 = U0494-A.2: IC buffer open drain, 1.65V to 5.5V, 32mA sink current, SOT-5X3 1.6mmx1.6mm; Manufacturer: Texas Instruments; Code Arduino: U0494

## Sheet PCIE.SchDoc: PCIE
size A3; SheetNumber: 24; SheetTotal: 51
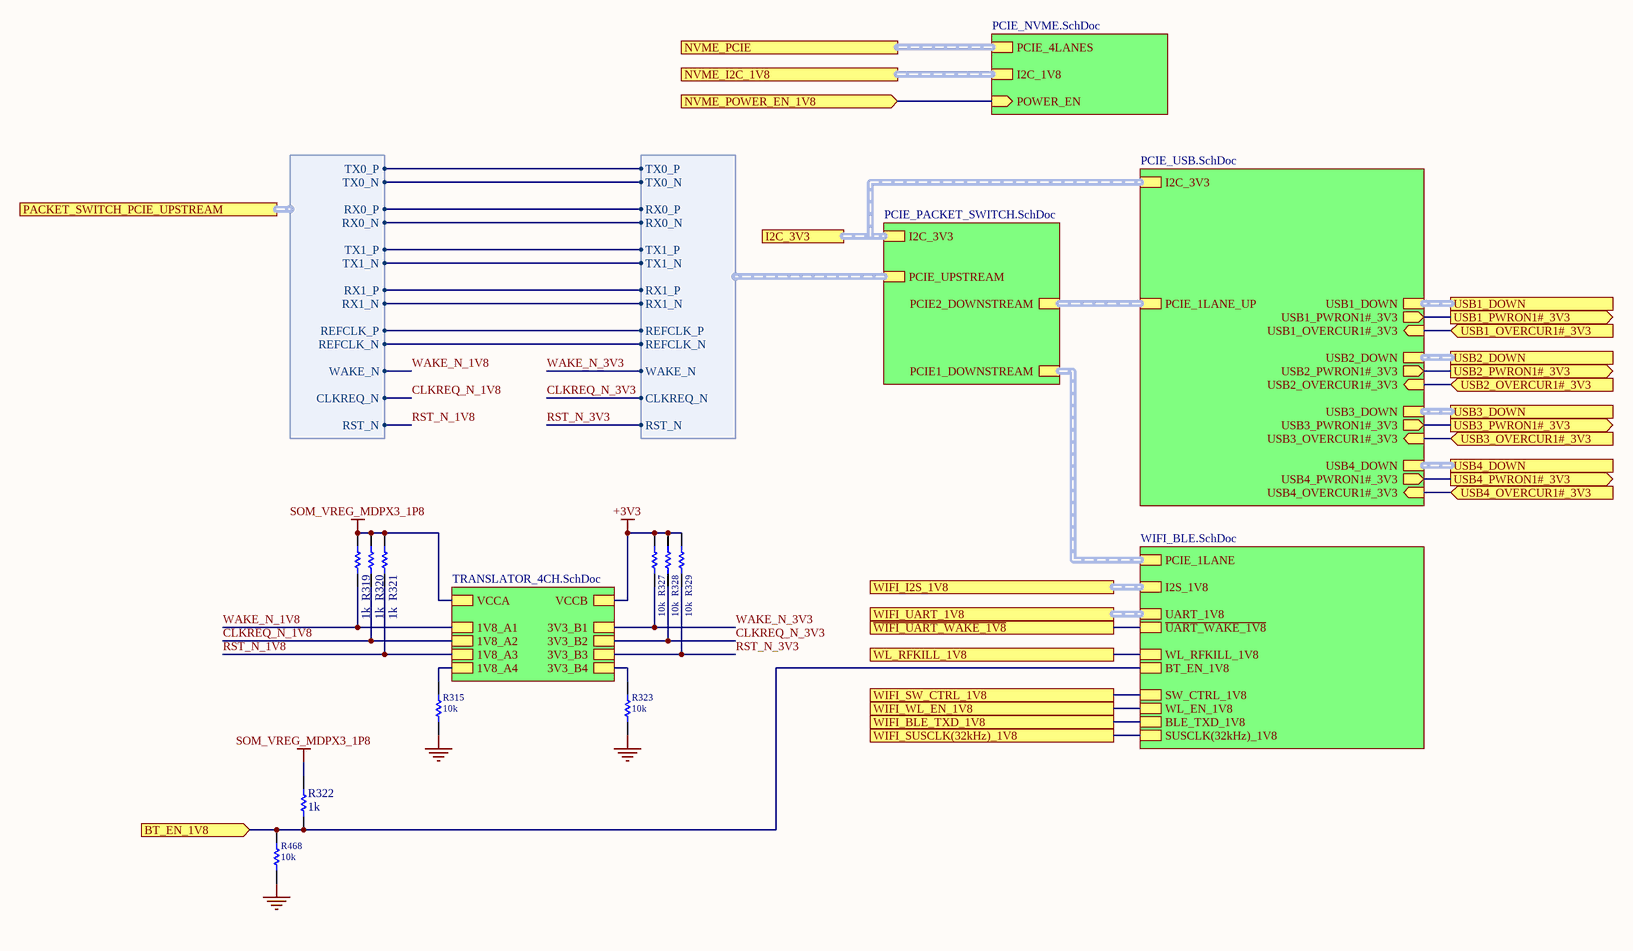
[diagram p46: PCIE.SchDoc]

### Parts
R315  value 10k  [RES-0201]  (hidden comment: RC0201FR-0710KL)
R319  value 1k  [RES-0201]  (hidden comment: RC0201FR-071KL)
R320  value 1k  [RES-0201]  (hidden comment: RC0201FR-071KL)
R321  value 1k  [RES-0201]  (hidden comment: RC0201FR-071KL)
R322  value 1k  [RES-0201]  (hidden comment: RC0201FR-071KL)
R323  value 10k  [RES-0201]  (hidden comment: RC0201FR-0710KL)
R327  value 10k  [RES-0201]  (hidden comment: RC0201FR-0710KL)
R328  value 10k  [RES-0201]  (hidden comment: RC0201FR-0710KL)
R329  value 10k  [RES-0201]  (hidden comment: RC0201FR-0710KL)
R468  value 10k  [RES-0201]  (hidden comment: RC0201FR-0710KL)

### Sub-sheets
U_PCIE_NVME = PCIE_NVME.SchDoc: POWER_EN (in), PCIE_4LANES (harness SOM_MD_PCIE1), I2C_1V8 (harness I2C)
U_PCIE_PACKET_SWITCH = PCIE_PACKET_SWITCH.SchDoc: PCIE_UPSTREAM (harness SOM_MD_PCIE0), I2C_3V3 (harness I2C), PCIE1_DOWNSTREAM (harness PCIE_1LANE), PCIE2_DOWNSTREAM (harness PCIE_1LANE)
U_PCIE_USB = PCIE_USB.SchDoc: USB1_DOWN (harness SOM_MD_USB0), USB1_PWRON1#_3V3 (out), USB1_OVERCUR1#_3V3 (in), USB2_DOWN (harness SOM_MD_USB0), USB2_PWRON1#_3V3 (out), USB2_OVERCUR1#_3V3 (in), USB3_DOWN (harness SOM_MD_USB0), USB3_PWRON1#_3V3 (out), USB3_OVERCUR1#_3V3 (in), USB4_DOWN (harness SOM_MD_USB0), USB4_PWRON1#_3V3 (out), USB4_OVERCUR1#_3V3 (in), PCIE_1LANE_UP (harness PCIE_1LANE), I2C_3V3 (harness I2C)
U_TRANSLATOR_4CH = TRANSLATOR_4CH.SchDoc: 1V8_A1, 1V8_A2, 1V8_A3, 1V8_A4, 3V3_B1, 3V3_B2, 3V3_B3, 3V3_B4, VCCA, VCCB
U_WIFI_BLE = WIFI_BLE.SchDoc: PCIE_1LANE (harness PCIE_1LANE), I2S_1V8 (harness SOM_MD_I2S), WL_RFKILL_1V8, UART_1V8 (harness SOM_MD_UART_FLCRTL), ~{UART_WAKE_1V8}, SW_CTRL_1V8, WL_EN_1V8, BLE_TXD_1V8, SUSCLK(32kHz)_1V8, BT_EN_1V8

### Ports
BT_EN_1V8 (in), I2C_3V3, NVME_I2C_1V8, NVME_PCIE, NVME_POWER_EN_1V8 (in), PACKET_SWITCH_PCIE_UPSTREAM (harness SOM_MD_PCIE0), USB1_DOWN, USB1_OVERCUR1#_3V3 (in), USB1_PWRON1#_3V3 (out), USB2_DOWN, USB2_OVERCUR1#_3V3 (in), USB2_PWRON1#_3V3 (out), USB3_DOWN (harness SOM_MD_USB0), USB3_OVERCUR1#_3V3 (in), USB3_PWRON1#_3V3 (out), USB4_DOWN, USB4_OVERCUR1#_3V3 (in), USB4_PWRON1#_3V3 (out), WIFI_BLE_TXD_1V8, WIFI_I2S_1V8, WIFI_SUSCLK(32kHz)_1V8, WIFI_SW_CTRL_1V8, WIFI_UART_1V8, WIFI_WL_EN_1V8, WL_RFKILL_1V8, ~{WIFI_UART_WAKE_1V8}

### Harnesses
SOM_MD_PCIE0: RX0_N, RX0_P, TX0_P, TX0_N, RX1_N, RX1_P, TX1_P, TX1_N, REFCLK_N, REFCLK_P, WAKE_N, CLKREQ_N, RST_N

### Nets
+3V3: R327.1 R328.1 R329.1 ; sheet U_TRANSLATOR_4CH/VCCB
GND: R315.1 R323.1 R468.1
SOM_VREG_MDPX3_1P8: R319.1 R320.1 R321.1 R322.2 ; sheet U_TRANSLATOR_4CH/VCCA
CLKREQ_N_1V8: R320.2 ; sheet U_TRANSLATOR_4CH/1V8_A2, port PACKET_SWITCH_PCIE_UPSTREAM.CLKREQ_N
CLKREQ_N_3V3: R328.2 ; sheet U_TRANSLATOR_4CH/3V3_B2, sheet U_PCIE_PACKET_SWITCH/PCIE_UPSTREAM.CLKREQ_N
MD_GPIO_51: port NVME_POWER_EN_1V8, sheet U_PCIE_NVME/POWER_EN
MD_GPIO_54: port WL_RFKILL_1V8, sheet U_WIFI_BLE/WL_RFKILL_1V8
MD_GPIO_55: R322.1 R468.2 ; port BT_EN_1V8, sheet U_WIFI_BLE/BT_EN_1V8
MD_GPIO_56: port WIFI_WL_EN_1V8, sheet U_WIFI_BLE/WL_EN_1V8
MD_GPIO_65: port ~{WIFI_UART_WAKE_1V8}, sheet U_WIFI_BLE/~{UART_WAKE_1V8}
MD_GPIO_100: port WIFI_SW_CTRL_1V8, sheet U_WIFI_BLE/SW_CTRL_1V8
MD_GPIO_101: port WIFI_BLE_TXD_1V8, sheet U_WIFI_BLE/BLE_TXD_1V8
MD_PCIE0_2LANES.REFCLK_N: port PACKET_SWITCH_PCIE_UPSTREAM.REFCLK_N, sheet U_PCIE_PACKET_SWITCH/PCIE_UPSTREAM.REFCLK_N
MD_PCIE0_2LANES.REFCLK_P: port PACKET_SWITCH_PCIE_UPSTREAM.REFCLK_P, sheet U_PCIE_PACKET_SWITCH/PCIE_UPSTREAM.REFCLK_P
MD_PCIE0_2LANES.RX0_N: port PACKET_SWITCH_PCIE_UPSTREAM.RX0_N, sheet U_PCIE_PACKET_SWITCH/PCIE_UPSTREAM.RX0_N
MD_PCIE0_2LANES.RX0_P: port PACKET_SWITCH_PCIE_UPSTREAM.RX0_P, sheet U_PCIE_PACKET_SWITCH/PCIE_UPSTREAM.RX0_P
MD_PCIE0_2LANES.RX1_N: port PACKET_SWITCH_PCIE_UPSTREAM.RX1_N, sheet U_PCIE_PACKET_SWITCH/PCIE_UPSTREAM.RX1_N
MD_PCIE0_2LANES.RX1_P: port PACKET_SWITCH_PCIE_UPSTREAM.RX1_P, sheet U_PCIE_PACKET_SWITCH/PCIE_UPSTREAM.RX1_P
MD_PCIE0_2LANES.TX0_N: port PACKET_SWITCH_PCIE_UPSTREAM.TX0_N, sheet U_PCIE_PACKET_SWITCH/PCIE_UPSTREAM.TX0_N
MD_PCIE0_2LANES.TX0_P: port PACKET_SWITCH_PCIE_UPSTREAM.TX0_P, sheet U_PCIE_PACKET_SWITCH/PCIE_UPSTREAM.TX0_P
MD_PCIE0_2LANES.TX1_N: port PACKET_SWITCH_PCIE_UPSTREAM.TX1_N, sheet U_PCIE_PACKET_SWITCH/PCIE_UPSTREAM.TX1_N
MD_PCIE0_2LANES.TX1_P: port PACKET_SWITCH_PCIE_UPSTREAM.TX1_P, sheet U_PCIE_PACKET_SWITCH/PCIE_UPSTREAM.TX1_P
RST_N_1V8: R321.2 ; sheet U_TRANSLATOR_4CH/1V8_A3, port PACKET_SWITCH_PCIE_UPSTREAM.RST_N  [project net GPIO_2]
RST_N_3V3: R329.2 ; sheet U_TRANSLATOR_4CH/3V3_B3, sheet U_PCIE_PACKET_SWITCH/PCIE_UPSTREAM.RST_N
SLEEP_CLK: port WIFI_SUSCLK(32kHz)_1V8, sheet U_WIFI_BLE/SUSCLK(32kHz)_1V8
WAKE_N_1V8: R319.2 ; sheet U_TRANSLATOR_4CH/1V8_A1, port PACKET_SWITCH_PCIE_UPSTREAM.WAKE_N  [project net GPIO_0]
WAKE_N_3V3: R327.2 ; sheet U_TRANSLATOR_4CH/3V3_B1, sheet U_PCIE_PACKET_SWITCH/PCIE_UPSTREAM.WAKE_N
NetJOMEGA_54: port USB1_PWRON1#_3V3, sheet U_PCIE_USB/USB1_PWRON1#_3V3
NetJOMEGA_56: port USB1_OVERCUR1#_3V3, sheet U_PCIE_USB/USB1_OVERCUR1#_3V3
NetJOMEGA_58: port USB3_PWRON1#_3V3, sheet U_PCIE_USB/USB3_PWRON1#_3V3
NetJOMEGA_60: port USB3_OVERCUR1#_3V3, sheet U_PCIE_USB/USB3_OVERCUR1#_3V3
NetR154_2: port USB4_PWRON1#_3V3, sheet U_PCIE_USB/USB4_PWRON1#_3V3
NetR182_2: port USB2_PWRON1#_3V3, sheet U_PCIE_USB/USB2_PWRON1#_3V3
NetR315_2: R315.2 ; sheet U_TRANSLATOR_4CH/1V8_A4
NetR323_2: R323.2 ; sheet U_TRANSLATOR_4CH/3V3_B4
NetU24_A37: port USB2_OVERCUR1#_3V3, sheet U_PCIE_USB/USB2_OVERCUR1#_3V3
NetU24_B45: port USB4_OVERCUR1#_3V3, sheet U_PCIE_USB/USB4_OVERCUR1#_3V3

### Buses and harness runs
harness port I2C_3V3 = sheet U_PCIE_PACKET_SWITCH/I2C_3V3 = sheet U_PCIE_USB/I2C_3V3
harness port NVME_I2C_1V8 = sheet U_PCIE_NVME/I2C_1V8
harness port NVME_PCIE = sheet U_PCIE_NVME/PCIE_4LANES
harness port USB1_DOWN = sheet U_PCIE_USB/USB1_DOWN
harness port USB2_DOWN = sheet U_PCIE_USB/USB2_DOWN
harness port USB3_DOWN = sheet U_PCIE_USB/USB3_DOWN
harness port USB4_DOWN = sheet U_PCIE_USB/USB4_DOWN
harness port WIFI_I2S_1V8 = sheet U_WIFI_BLE/I2S_1V8
harness port WIFI_UART_1V8 = sheet U_WIFI_BLE/UART_1V8
harness sheet U_PCIE_PACKET_SWITCH/PCIE1_DOWNSTREAM = sheet U_WIFI_BLE/PCIE_1LANE
harness sheet U_PCIE_PACKET_SWITCH/PCIE2_DOWNSTREAM = sheet U_PCIE_USB/PCIE_1LANE_UP

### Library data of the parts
R315 R323 R327-R329 R468 = R0145-A.21: as R317 on sheet HEADERS_JCTL
R319-R322 = R0195-A.22: as R166 on sheet HEADERS_JCTL

## Sheet PCIE_PACKET_SWITCH.SchDoc: PCIE PACKET SWITCH
size A3; Author: Silvio Navaretti; CompanyName: ARDUINO; DrawnBy: Silvio Navaretti; Engineer: Silvio Navaretti; Organization: ARDUINO; SheetNumber: 25; SheetTotal: 51; RevAuthor: Silvio Navaretti
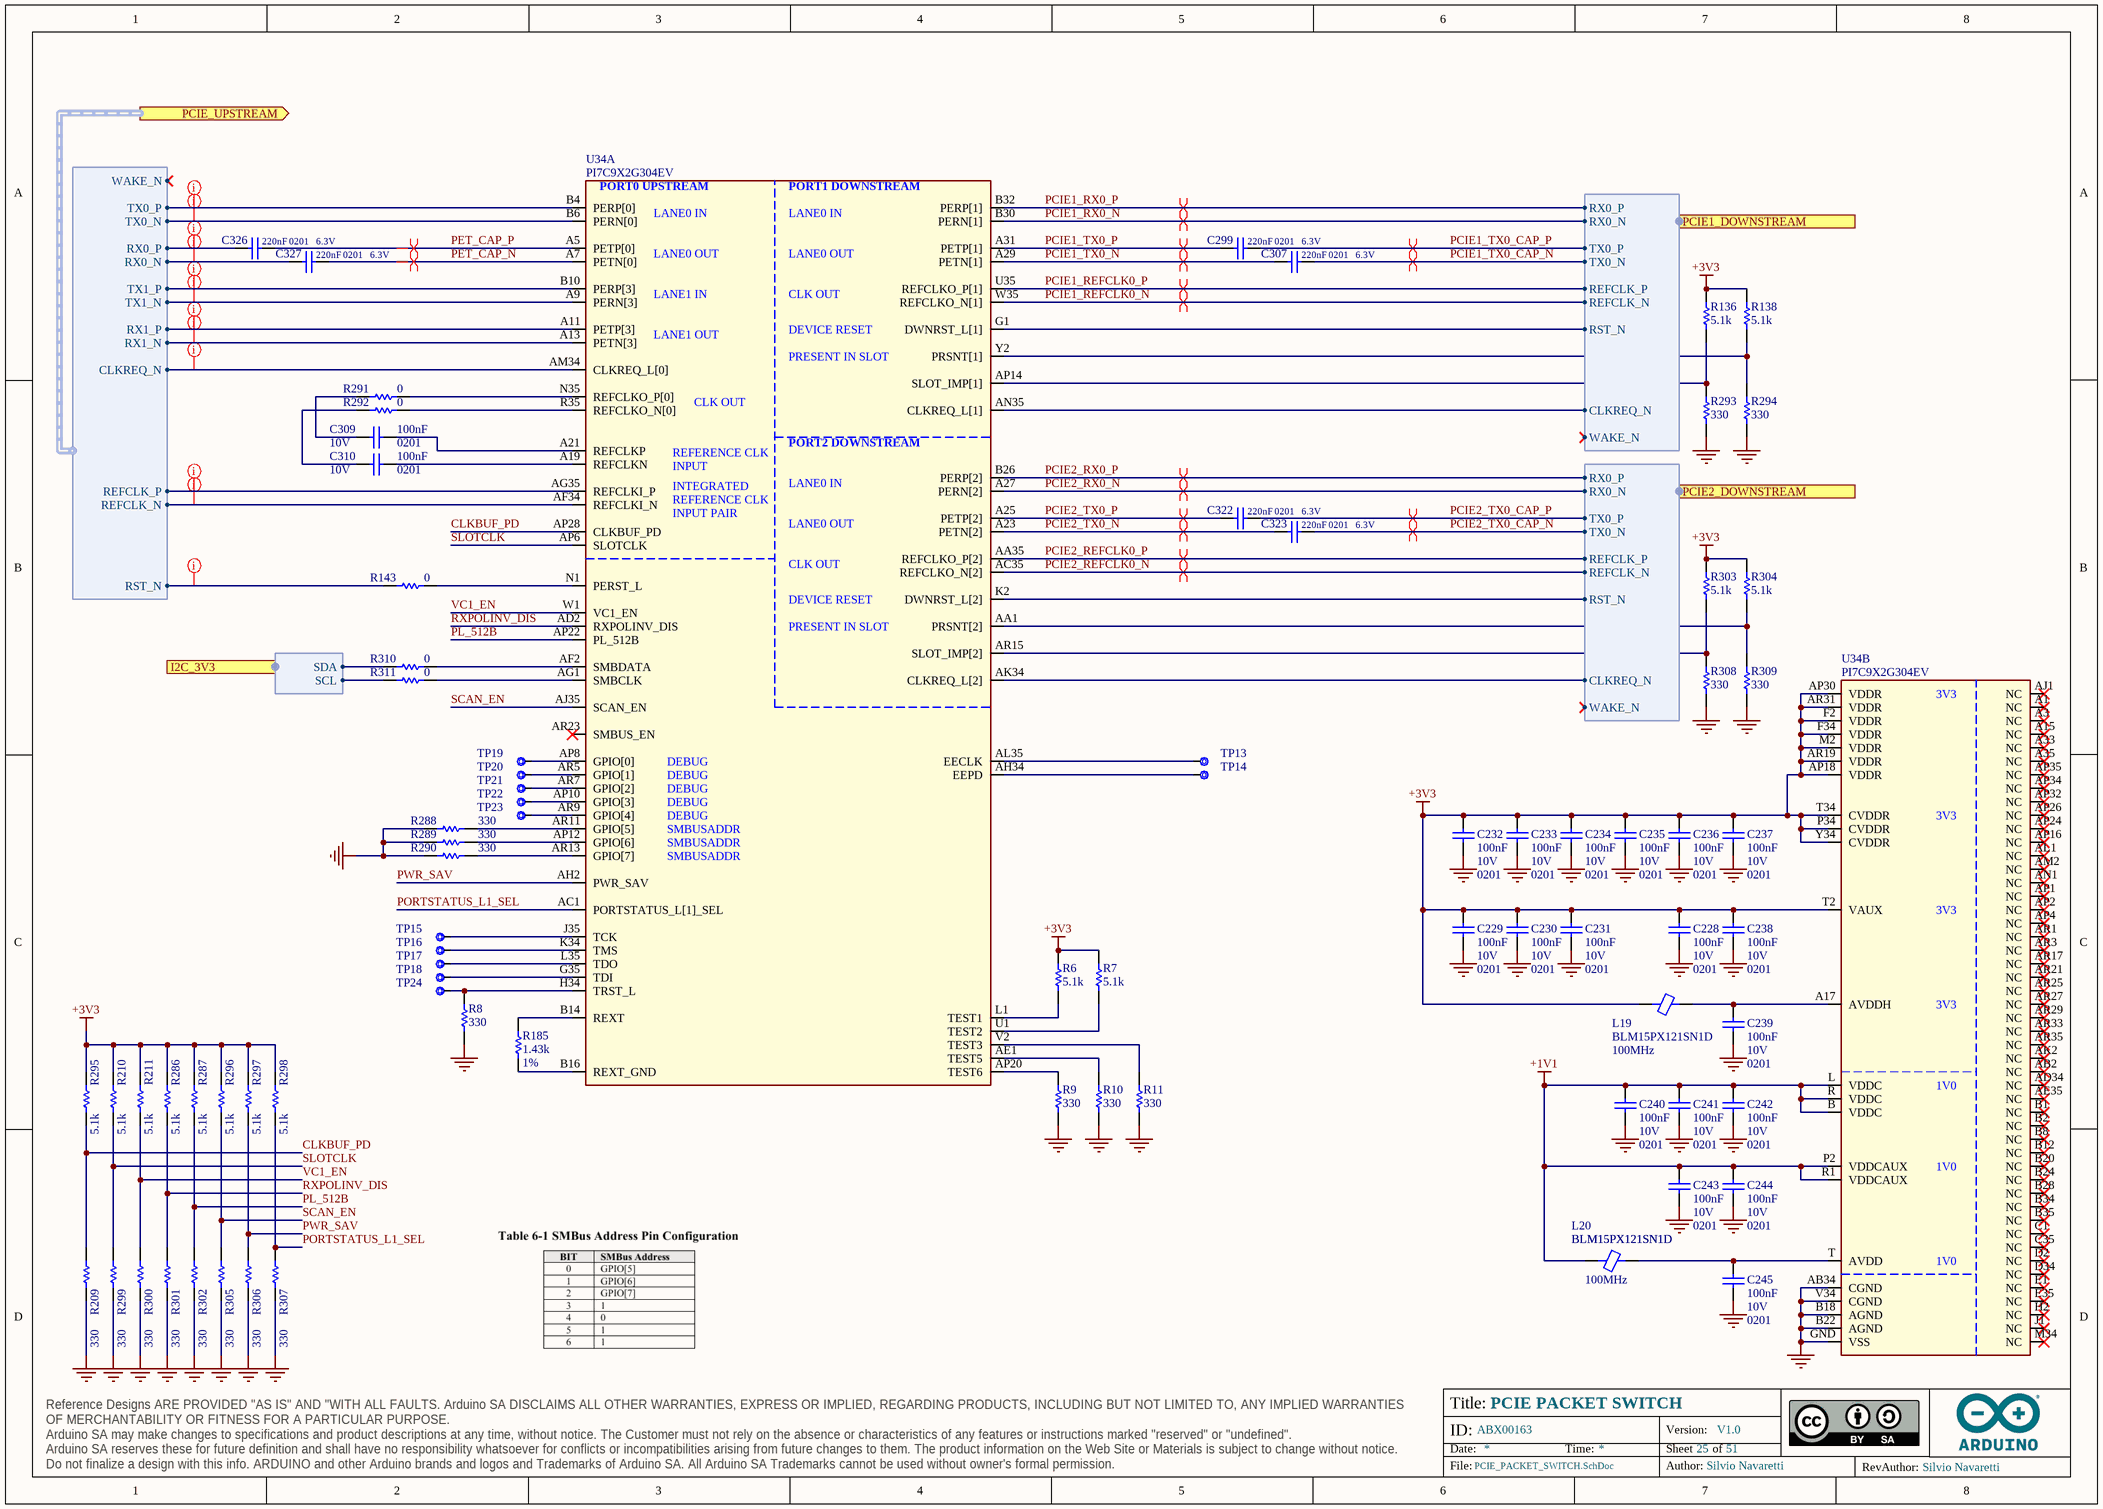
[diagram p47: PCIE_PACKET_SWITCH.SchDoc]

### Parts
C228  value 100nF  Voltage: 10V  Case Code (Imperial): 0201  [CAP-0201]  (hidden comment: CL03A104KP3NNNC)
C229  value 100nF  Voltage: 10V  Case Code (Imperial): 0201  [CAP-0201]  (hidden comment: CL03A104KP3NNNC)
C230  value 100nF  Voltage: 10V  Case Code (Imperial): 0201  [CAP-0201]  (hidden comment: CL03A104KP3NNNC)
C231  value 100nF  Voltage: 10V  Case Code (Imperial): 0201  [CAP-0201]  (hidden comment: CL03A104KP3NNNC)
C232  value 100nF  Voltage: 10V  Case Code (Imperial): 0201  [CAP-0201]  (hidden comment: CL03A104KP3NNNC)
C233  value 100nF  Voltage: 10V  Case Code (Imperial): 0201  [CAP-0201]  (hidden comment: CL03A104KP3NNNC)
C234  value 100nF  Voltage: 10V  Case Code (Imperial): 0201  [CAP-0201]  (hidden comment: CL03A104KP3NNNC)
C235  value 100nF  Voltage: 10V  Case Code (Imperial): 0201  [CAP-0201]  (hidden comment: CL03A104KP3NNNC)
C236  value 100nF  Voltage: 10V  Case Code (Imperial): 0201  [CAP-0201]  (hidden comment: CL03A104KP3NNNC)
C237  value 100nF  Voltage: 10V  Case Code (Imperial): 0201  [CAP-0201]  (hidden comment: CL03A104KP3NNNC)
C238  value 100nF  Voltage: 10V  Case Code (Imperial): 0201  [CAP-0201]  (hidden comment: CL03A104KP3NNNC)
C239  value 100nF  Voltage: 10V  Case Code (Imperial): 0201  [CAP-0201]  (hidden comment: CL03A104KP3NNNC)
C240  value 100nF  Voltage: 10V  Case Code (Imperial): 0201  [CAP-0201]  (hidden comment: CL03A104KP3NNNC)
C241  value 100nF  Voltage: 10V  Case Code (Imperial): 0201  [CAP-0201]  (hidden comment: CL03A104KP3NNNC)
C242  value 100nF  Voltage: 10V  Case Code (Imperial): 0201  [CAP-0201]  (hidden comment: CL03A104KP3NNNC)
C243  value 100nF  Voltage: 10V  Case Code (Imperial): 0201  [CAP-0201]  (hidden comment: CL03A104KP3NNNC)
C244  value 100nF  Voltage: 10V  Case Code (Imperial): 0201  [CAP-0201]  (hidden comment: CL03A104KP3NNNC)
C245  value 100nF  Voltage: 10V  Case Code (Imperial): 0201  [CAP-0201]  (hidden comment: CL03A104KP3NNNC)
C299  value 220nF  Case Code (Imperial): 0201  Voltage: 6.3V  [CAP-0201]  (hidden comment: GRM033R60J224ME15D)
C307  value 220nF  Case Code (Imperial): 0201  Voltage: 6.3V  [CAP-0201]  (hidden comment: GRM033R60J224ME15D)
C309  value 100nF  Voltage: 10V  Case Code (Imperial): 0201  [CAP-0201]  (hidden comment: CL03A104KP3NNNC)
C310  value 100nF  Voltage: 10V  Case Code (Imperial): 0201  [CAP-0201]  (hidden comment: CL03A104KP3NNNC)
C322  value 220nF  Case Code (Imperial): 0201  Voltage: 6.3V  [CAP-0201]  (hidden comment: GRM033R60J224ME15D)
C323  value 220nF  Case Code (Imperial): 0201  Voltage: 6.3V  [CAP-0201]  (hidden comment: GRM033R60J224ME15D)
C326  value 220nF  Case Code (Imperial): 0201  Voltage: 6.3V  [CAP-0201]  (hidden comment: GRM033R60J224ME15D)
C327  value 220nF  Case Code (Imperial): 0201  Voltage: 6.3V  [CAP-0201]  (hidden comment: GRM033R60J224ME15D)
L19  BLM15PX121SN1D  Test Frequency: 100MHz  [L-0402]
L20  BLM15PX121SN1D  Test Frequency: 100MHz  [L-0402]
R6  value 5.1k  [RES-0201]  (hidden comment: ERJ-1GNF5101C)
R7  value 5.1k  [RES-0201]  (hidden comment: ERJ-1GNF5101C)
R8  value 330  [RES-0201]  (hidden comment: AC0201FR-07330RL)
R9  value 330  [RES-0201]  (hidden comment: AC0201FR-07330RL)
R10  value 330  [RES-0201]  (hidden comment: AC0201FR-07330RL)
R11  value 330  [RES-0201]  (hidden comment: AC0201FR-07330RL)
R136  value 5.1k  [RES-0201]  (hidden comment: ERJ-1GNF5101C)
R138  value 5.1k  [RES-0201]  (hidden comment: ERJ-1GNF5101C)
R143  value 0  [RES-0201]  (hidden comment: CRCW02010000Z0ED)
R185  value 1.43k  Tolerance: 1%  [RES-0201]  (hidden comment: RC0201FR-071K43L)
R209  value 330  [RES-0201]  (hidden comment: AC0201FR-07330RL)
R210  value 5.1k  [RES-0201]  (hidden comment: ERJ-1GNF5101C)
R211  value 5.1k  [RES-0201]  (hidden comment: ERJ-1GNF5101C)
R286  value 5.1k  [RES-0201]  (hidden comment: ERJ-1GNF5101C)
R287  value 5.1k  [RES-0201]  (hidden comment: ERJ-1GNF5101C)
R288  value 330  [RES-0201]  (hidden comment: AC0201FR-07330RL)
R289  value 330  [RES-0201]  (hidden comment: AC0201FR-07330RL)
R290  value 330  [RES-0201]  (hidden comment: AC0201FR-07330RL)
R291  value 0  [RES-0201]  (hidden comment: CRCW02010000Z0ED)
R292  value 0  [RES-0201]  (hidden comment: CRCW02010000Z0ED)
R293  value 330  [RES-0201]  (hidden comment: AC0201FR-07330RL)
R294  value 330  [RES-0201]  (hidden comment: AC0201FR-07330RL)
R295  value 5.1k  [RES-0201]  (hidden comment: ERJ-1GNF5101C)
R296  value 5.1k  [RES-0201]  (hidden comment: ERJ-1GNF5101C)
R297  value 5.1k  [RES-0201]  (hidden comment: ERJ-1GNF5101C)
R298  value 5.1k  [RES-0201]  (hidden comment: ERJ-1GNF5101C)
R299  value 330  [RES-0201]  (hidden comment: AC0201FR-07330RL)
R300  value 330  [RES-0201]  (hidden comment: AC0201FR-07330RL)
R301  value 330  [RES-0201]  (hidden comment: AC0201FR-07330RL)
R302  value 330  [RES-0201]  (hidden comment: AC0201FR-07330RL)
R303  value 5.1k  [RES-0201]  (hidden comment: ERJ-1GNF5101C)
R304  value 5.1k  [RES-0201]  (hidden comment: ERJ-1GNF5101C)
R305  value 330  [RES-0201]  (hidden comment: AC0201FR-07330RL)
R306  value 330  [RES-0201]  (hidden comment: AC0201FR-07330RL)
R307  value 330  [RES-0201]  (hidden comment: AC0201FR-07330RL)
R308  value 330  [RES-0201]  (hidden comment: AC0201FR-07330RL)
R309  value 330  [RES-0201]  (hidden comment: AC0201FR-07330RL)
R310  value 0  [RES-0201]  (hidden comment: CRCW02010000Z0ED)
R311  value 0  [RES-0201]  (hidden comment: CRCW02010000Z0ED)
TP13  Test point 1.00mm  [TP-1.00MM]  (value not drawn)  (no BOM)
TP14  Test point 1.00mm  [TP-1.00MM]  (value not drawn)  (no BOM)
TP15  Test point 1.00mm  [TP-1.00MM]  (value not drawn)  (no BOM)
TP16  Test point 1.00mm  [TP-1.00MM]  (value not drawn)  (no BOM)
TP17  Test point 1.00mm  [TP-1.00MM]  (value not drawn)  (no BOM)
TP18  Test point 1.00mm  [TP-1.00MM]  (value not drawn)  (no BOM)
TP19  Test point 1.00mm  [TP-1.00MM]  (value not drawn)  (no BOM)
TP20  Test point 1.00mm  [TP-1.00MM]  (value not drawn)  (no BOM)
TP21  Test point 1.00mm  [TP-1.00MM]  (value not drawn)  (no BOM)
TP22  Test point 1.00mm  [TP-1.00MM]  (value not drawn)  (no BOM)
TP23  Test point 1.00mm  [TP-1.00MM]  (value not drawn)  (no BOM)
TP24  Test point 1.00mm  [TP-1.00MM]  (value not drawn)  (no BOM)
U34  PI7C9X2G304EV  [PI7C9X2G304EV-Footprint-1]  (parts A,B of 2)

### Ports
I2C_3V3 (out, harness I2C), PCIE1_DOWNSTREAM (out, harness PCIE_1LANE), PCIE2_DOWNSTREAM (out, harness PCIE_1LANE), PCIE_UPSTREAM (out, harness SOM_MD_PCIE0)

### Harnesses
PCIE_1LANE: RX0_N, RX0_P, TX0_P, TX0_N, REFCLK_N, REFCLK_P, WAKE_N, CLKREQ_N, RST_N
I2C: SDA, SCL
SOM_MD_PCIE0: RX0_N, RX0_P, TX0_P, TX0_N, RX1_N, RX1_P, TX1_P, TX1_N, REFCLK_N, REFCLK_P, WAKE_N, CLKREQ_N, RST_N

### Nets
+1V1: C240.2 C241.2 C242.2 C243.2 C244.2 L20.1 U34.B(VDDC) U34.L(VDDC) U34.P2(VDDCAUX) U34.R(VDDC) U34.R1(VDDCAUX)
+3V3: C228.2 C229.2 C230.2 C231.2 C232.2 C233.2 C234.2 C235.2 C236.2 C237.2 C238.2 L19.1 R6.2 R7.2 R136.2 R138.2 R210.2 R211.2 R286.2 R287.2 R295.2 R296.2 R297.2 R298.2 R303.2 R304.2 U34.AP18(VDDR) U34.AP30(VDDR) U34.AR19(VDDR) U34.AR31(VDDR) U34.F2(VDDR) U34.F34(VDDR) U34.M2(VDDR) U34.P34(CVDDR) U34.T2(VAUX) U34.T34(CVDDR) U34.Y34(CVDDR)
GND: C228.1 C229.1 C230.1 C231.1 C232.1 C233.1 C234.1 C235.1 C236.1 C237.1 C238.1 C239.1 C240.1 C241.1 C242.1 C243.1 C244.1 C245.1 R8.1 R9.1 R10.1 R11.1 R209.1 R288.2 R289.2 R290.2 R293.1 R294.1 R299.1 R300.1 R301.1 R302.1 R305.1 R306.1 R307.1 R308.1 R309.1 U34.AB34(CGND) U34.B18(AGND) U34.B22(AGND) U34.GND(VSS) U34.V34(CGND)
CLKBUF_PD: R209.2 R295.1 U34.AP28(CLKBUF_PD)  [project net CLKBUF_PD_25]
CLKREQ_N_3V3: U34.AM34(CLKREQ_L[0]) ; port PCIE_UPSTREAM.CLKREQ_N
MD_PCIE0_2LANES.REFCLK_N: U34.AF34(REFCLKI_N) ; port PCIE_UPSTREAM.REFCLK_N
MD_PCIE0_2LANES.REFCLK_P: U34.AG35(REFCLKI_P) ; port PCIE_UPSTREAM.REFCLK_P
MD_PCIE0_2LANES.RX0_N: C327.2 ; port PCIE_UPSTREAM.RX0_N
MD_PCIE0_2LANES.RX0_P: C326.2 ; port PCIE_UPSTREAM.RX0_P
MD_PCIE0_2LANES.RX1_N: U34.A13(PETN[3]) ; port PCIE_UPSTREAM.RX1_N
MD_PCIE0_2LANES.RX1_P: U34.A11(PETP[3]) ; port PCIE_UPSTREAM.RX1_P
MD_PCIE0_2LANES.TX0_N: U34.B6(PERN[0]) ; port PCIE_UPSTREAM.TX0_N
MD_PCIE0_2LANES.TX0_P: U34.B4(PERP[0]) ; port PCIE_UPSTREAM.TX0_P
MD_PCIE0_2LANES.TX1_N: U34.A9(PERN[3]) ; port PCIE_UPSTREAM.TX1_N
MD_PCIE0_2LANES.TX1_P: U34.B10(PERP[3]) ; port PCIE_UPSTREAM.TX1_P
MD_QUP1_SE4_I2C_3V3.SCL: R311.2 ; port I2C_3V3.SCL
MD_QUP1_SE4_I2C_3V3.SDA: R310.2 ; port I2C_3V3.SDA
PCIE1_REFCLK0_N: U34.W35(REFCLKO_N[1]) ; port PCIE1_DOWNSTREAM.REFCLK_N
PCIE1_REFCLK0_P: U34.U35(REFCLKO_P[1]) ; port PCIE1_DOWNSTREAM.REFCLK_P
PCIE1_RX0_N: U34.B30(PERN[1]) ; port PCIE1_DOWNSTREAM.RX0_N
PCIE1_RX0_P: U34.B32(PERP[1]) ; port PCIE1_DOWNSTREAM.RX0_P
PCIE1_TX0_CAP_N: C307.1 ; port PCIE1_DOWNSTREAM.TX0_N
PCIE1_TX0_CAP_P: C299.1 ; port PCIE1_DOWNSTREAM.TX0_P
PCIE1_TX0_N: C307.2 U34.A29(PETN[1])  [project net PCIE1_TX0_N_25]
PCIE1_TX0_P: C299.2 U34.A31(PETP[1])  [project net PCIE1_TX0_P_25]
PCIE2_REFCLK0_N: U34.AC35(REFCLKO_N[2]) ; port PCIE2_DOWNSTREAM.REFCLK_N
PCIE2_REFCLK0_P: U34.AA35(REFCLKO_P[2]) ; port PCIE2_DOWNSTREAM.REFCLK_P
PCIE2_RX0_N: U34.A27(PERN[2]) ; port PCIE2_DOWNSTREAM.RX0_N
PCIE2_RX0_P: U34.B26(PERP[2]) ; port PCIE2_DOWNSTREAM.RX0_P
PCIE2_TX0_CAP_N: C323.1 ; port PCIE2_DOWNSTREAM.TX0_N
PCIE2_TX0_CAP_P: C322.1 ; port PCIE2_DOWNSTREAM.TX0_P
PCIE2_TX0_N: C323.2 U34.A23(PETN[2])  [project net PCIE2_TX0_N_25]
PCIE2_TX0_P: C322.2 U34.A25(PETP[2])  [project net PCIE2_TX0_P_25]
PET_CAP_N: C327.1 U34.A7(PETN[0])  [project net PET_CAP_N_25]
PET_CAP_P: C326.1 U34.A5(PETP[0])  [project net PET_CAP_P_25]
PL_512B: R287.1 R302.2 U34.AP22(PL_512B)  [project net PL_512B_25]
PORTSTATUS_L1_SEL: R298.1 R307.2 U34.AC1(PORTSTATUS_L[1]_SEL)  [project net PORTSTATUS_L1_SEL_25]
PWR_SAV: R297.1 R306.2 U34.AH2(PWR_SAV)  [project net PWR_SAV_25]
RST_N_3V3: R143.2 ; port PCIE_UPSTREAM.RST_N
RXPOLINV_DIS: R286.1 R301.2 U34.AD2(RXPOLINV_DIS)  [project net RXPOLINV_DIS_25]
SCAN_EN: R296.1 R305.2 U34.AJ35(SCAN_EN)  [project net SCAN_EN_25]
SLOTCLK: R210.1 R299.2 U34.AP6(SLOTCLK)  [project net SLOTCLK_25]
VC1_EN: R211.1 R300.2 U34.W1(VC1_EN)  [project net VC1_EN_25]
NetC239_2: C239.2 L19.2 U34.A17(AVDDH)
NetC245_2: C245.2 L20.2 U34.T(AVDD)
NetC309_1: C309.1 U34.A21(REFCLKP)
NetC309_2: C309.2 R291.1
NetC310_1: C310.1 U34.A19(REFCLKN)
NetC310_2: C310.2 R292.1
NetR6_1: R6.1 U34.L1(TEST1)
NetR7_1: R7.1 U34.U1(TEST2)
NetR8_2: R8.2 TP24.X U34.H34(TRST_L)
NetR9_2: R9.2 U34.AP20(TEST6)
NetR10_2: R10.2 U34.AE1(TEST5)
NetR11_2: R11.2 U34.V2(TEST3)
NetR136_1: R136.1 R293.2 U34.AP14(SLOT_IMP[1])
NetR138_1: R138.1 R294.2 U34.Y2(PRSNT[1])
NetR143_1: R143.1 U34.N1(PERST_L)
NetR185_1: R185.1 U34.B14(REXT)
NetR185_2: R185.2 U34.B16(REXT_GND)
NetR288_1: R288.1 U34.AR11(GPIO[5])
NetR289_1: R289.1 U34.AP12(GPIO[6])
NetR290_1: R290.1 U34.AR13(GPIO[7])
NetR291_2: R291.2 U34.N35(REFCLKO_P[0])
NetR292_2: R292.2 U34.R35(REFCLKO_N[0])
NetR303_1: R303.1 R308.2 U34.AR15(SLOT_IMP[2])
NetR304_1: R304.1 R309.2 U34.AA1(PRSNT[2])
NetR310_1: R310.1 U34.AF2(SMBDATA)
NetR311_1: R311.1 U34.AG1(SMBCLK)
NetR463_2: U34.AN35(CLKREQ_L[1]) ; port PCIE1_DOWNSTREAM.CLKREQ_N
NetR464_2: U34.G1(DWNRST_L[1]) ; port PCIE1_DOWNSTREAM.RST_N
NetTP13_X: TP13.X U34.AL35(EECLK)
NetTP14_X: TP14.X U34.AH34(EEPD)
NetTP15_X: TP15.X U34.J35(TCK)
NetTP16_X: TP16.X U34.K34(TMS)
NetTP17_X: TP17.X U34.L35(TDO)
NetTP18_X: TP18.X U34.G35(TDI)
NetTP19_X: TP19.X U34.AP8(GPIO[0])
NetTP20_X: TP20.X U34.AR5(GPIO[1])
NetTP21_X: TP21.X U34.AR7(GPIO[2])
NetTP22_X: TP22.X U34.AP10(GPIO[3])
NetTP23_X: TP23.X U34.AR9(GPIO[4])
NetU24_A40: U34.K2(DWNRST_L[2]) ; port PCIE2_DOWNSTREAM.RST_N
NetU24_B36: U34.AK34(CLKREQ_L[2]) ; port PCIE2_DOWNSTREAM.CLKREQ_N

Not connected (* = marked no-connect by the designer): U34 A1(NC)* A3(NC)* A15(NC)* A33(NC)* A35(NC)* AB2(NC)* AD34(NC)* AE35(NC)* AJ1(NC)* AK2(NC)* AL1(NC)* AM2(NC)* AN1(NC)* AP1(NC)* AP2(NC)* AP4(NC)* AP16(NC)* AP24(NC)* AP26(NC)* AP32(NC)* AP34(NC)* AP35(NC)* AR1(NC)* AR3(NC)* AR17(NC)* AR21(NC)* AR23(SMBUS_EN)* AR25(NC)* AR27(NC)* AR29(NC)* AR33(NC)* AR35(NC)* B1(NC)* B2(NC)* B8(NC)* B12(NC)* B20(NC)* B24(NC)* B28(NC)* B34(NC)* B35(NC)* C1(NC)* C35(NC)* D2(NC)* D34(NC)* E1(NC)* E35(NC)* H2(NC)* J1(NC)* M34(NC)*

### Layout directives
differential pair; differential pair class DIFF_PCIE_DOWN1: PCIE1_REFCLK0_N, PCIE1_REFCLK0_P, PCIE1_RX0_N, PCIE1_RX0_P, PCIE1_TX0_CAP_N, PCIE1_TX0_CAP_P, PCIE1_TX0_N_25, PCIE1_TX0_P_25
net class NET_PCIE_UP: CLKREQ_N_3V3, MD_PCIE0_2LANES.REFCLK_N, MD_PCIE0_2LANES.REFCLK_P, MD_PCIE0_2LANES.RX0_N, MD_PCIE0_2LANES.RX0_P, MD_PCIE0_2LANES.RX1_N, MD_PCIE0_2LANES.RX1_P, MD_PCIE0_2LANES.TX0_N, MD_PCIE0_2LANES.TX0_P, MD_PCIE0_2LANES.TX1_N, MD_PCIE0_2LANES.TX1_P, RST_N_3V3
differential pair; differential pair class DIFF_PCIE_DOWN2: PCIE2_REFCLK0_N, PCIE2_REFCLK0_P, PCIE2_RX0_N, PCIE2_RX0_P, PCIE2_TX0_CAP_N, PCIE2_TX0_CAP_P, PCIE2_TX0_N_25, PCIE2_TX0_P_25
differential pair; differential pair class DIFF_PCIE_PET: PET_CAP_N_25, PET_CAP_P_25

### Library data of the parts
C228-C245 C309 C310 = C0113-A.6: as C305 on sheet HEATSINK_FAN
C299 C307 C322 C323 C326 C327 = C0004-A.15: CAP CHIP 0201 220nF 20% 6.3V X5R; Manufacturer: Murata; Code Arduino: C0004
L19 L20 = I0028-A.10: FERRITE SMD 0402 120Ohm 25% 100MHz Ferrite 2A; Manufacturer: Murata; Inductance: 120µH; DC Resistance (DCR): 55mR; Code Arduino: I0028; Value: 120µH
R6 R7 R136 R138 R210 R211 R286 R287 R295-R298 R303 R304 = R0376-A.1: RES CHIP 0201 5k1 1% 1/20W; Manufacturer: Panasonic; Code Arduino: R0376; Power: 50mW; Temperature Coefficient: 200ppm
R8-R11 R209 R288-R290 R293 R294 R299-R302 R305-R309 = R0149-A.21: RES CHIP 0201 330R 1% 1/20W; Manufacturer: Yageo; Code Arduino: R0149; Power: 50mW; Temperature coefficient: 200ppm
R143 R291 R292 R310 R311 = R0140-A.21: as R508 on sheet HEADERS_JMEDIA_JMISC
R185 = R0400-A.1: RES CHIP 0201 1k43 1% 1/20W; Manufacturer: YAGEO; Power: 50mW; Temperature Coefficient: 200ppm; Code Arduino: R0400
TP13-TP24 = UT0013-A.6: Part Number: This is not a component
U34 = U0511-A.14: IC 3PCIe 2.0 Packet Switch 3-Port, 4-Lane aQFN136 10x10mm; Manufacturer: Diodes Incorporated; Code Arduino: U0511

## Sheet PCIE_NVME.SchDoc: PCIE_NVME
size A3; SheetNumber: 27; SheetTotal: 51
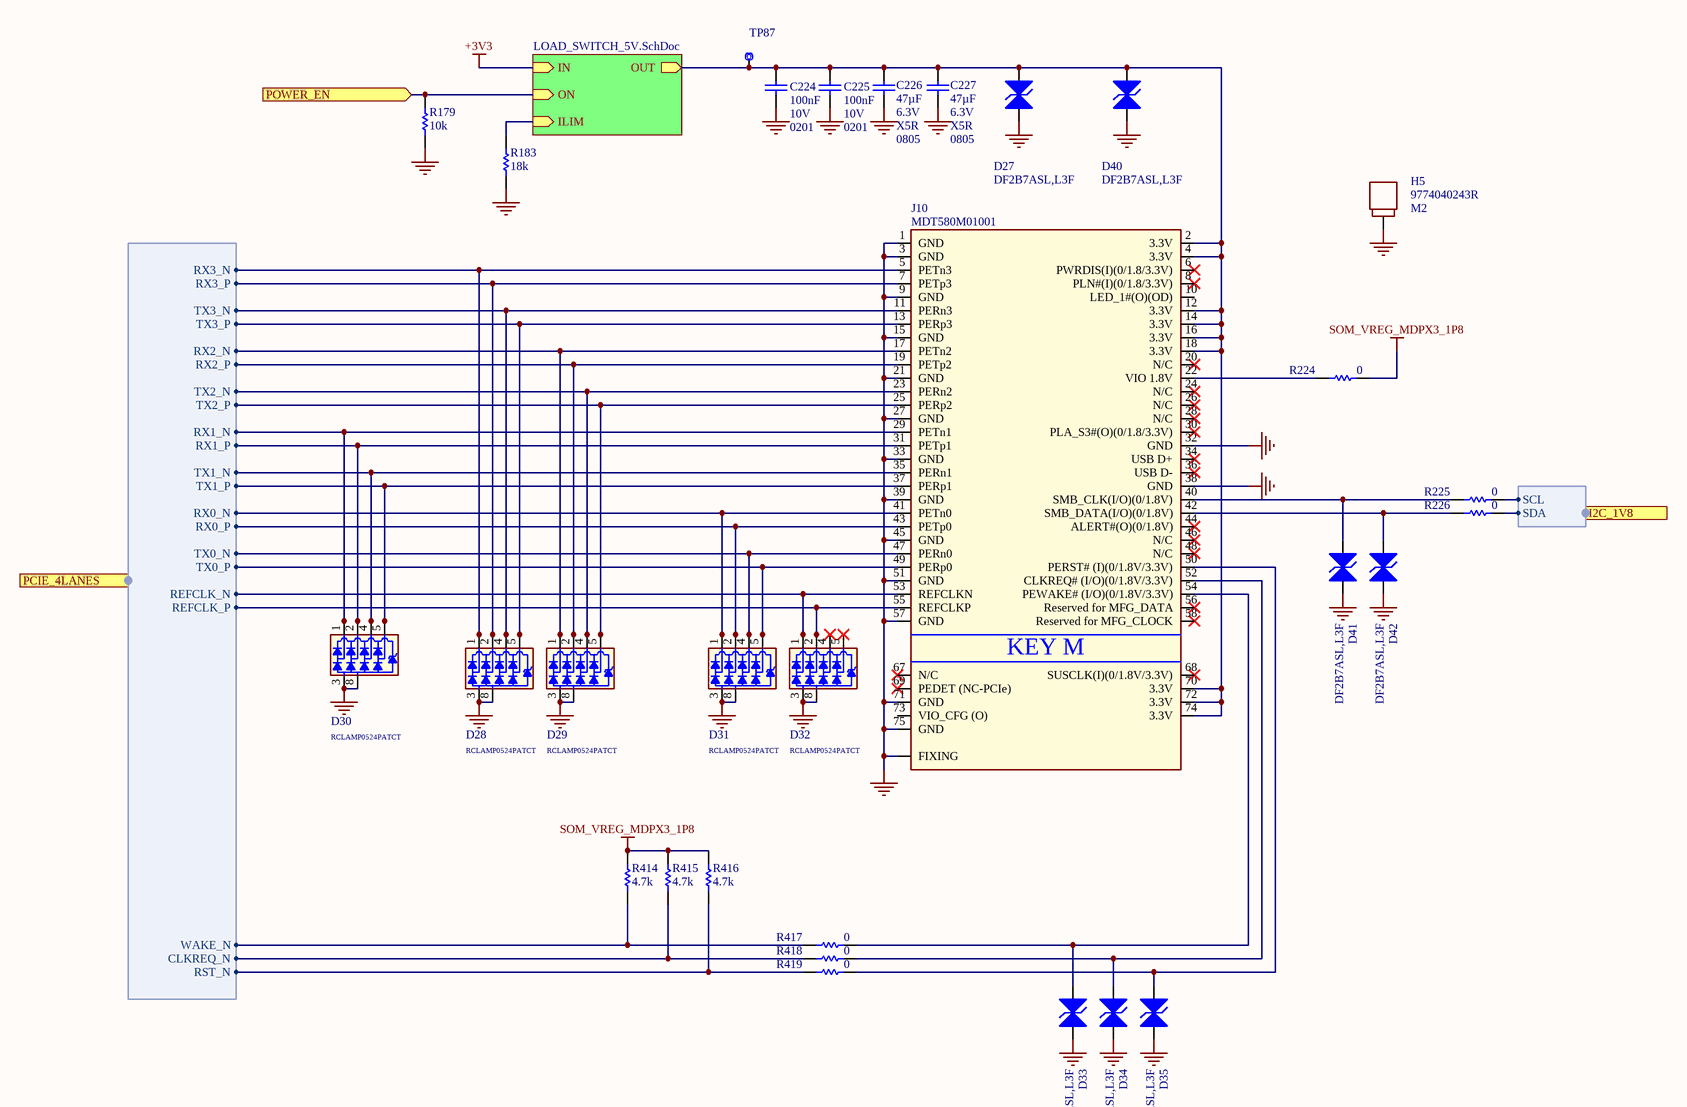
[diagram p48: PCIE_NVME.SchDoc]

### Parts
C224  value 100nF  Voltage: 10V  Case Code (Imperial): 0201  [CAP-0201]  (hidden comment: CL03A104KP3NNNC)
C225  value 100nF  Voltage: 10V  Case Code (Imperial): 0201  [CAP-0201]  (hidden comment: CL03A104KP3NNNC)
C226  value 47µF  Voltage: 6.3V  Dielectric: X5R  Case Code (Imperial): 0805  [CAP-0805]  (hidden comment: C0805C476M9PAC7800)
C227  value 47µF  Voltage: 6.3V  Dielectric: X5R  Case Code (Imperial): 0805  [CAP-0805]  (hidden comment: C0805C476M9PAC7800)
D27  DF2B7ASL,L3F  [DF2B7ASL,L3F]
D28  RCLAMP0524PATCT  [SLP2510P8]
D29  RCLAMP0524PATCT  [SLP2510P8]
D30  RCLAMP0524PATCT  [SLP2510P8]
D31  RCLAMP0524PATCT  [SLP2510P8]
D32  RCLAMP0524PATCT  [SLP2510P8]
D33  DF2B7ASL,L3F  [DF2B7ASL,L3F]
D34  DF2B7ASL,L3F  [DF2B7ASL,L3F]
D35  DF2B7ASL,L3F  [DF2B7ASL,L3F]
D40  DF2B7ASL,L3F  [DF2B7ASL,L3F]
D41  DF2B7ASL,L3F  [DF2B7ASL,L3F]
D42  DF2B7ASL,L3F  [DF2B7ASL,L3F]
H5  9774040243R  [9774040243R]
J10  MDT580M01001  [MDT580M01001]
R179  value 10k  [RES-0201]  (hidden comment: RC0201FR-0710KL)
R183  value 18k  [RES-0201]  (hidden comment: RC0201FR-0718KL)
R224  value 0  [RES-0201]  (hidden comment: CRCW02010000Z0ED)
R225  value 0  [RES-0201]  (hidden comment: CRCW02010000Z0ED)
R226  value 0  [RES-0201]  (hidden comment: CRCW02010000Z0ED)
R414  value 4.7k  [RES-0201]  (hidden comment: RC0201FR-074K7L)
R415  value 4.7k  [RES-0201]  (hidden comment: RC0201FR-074K7L)
R416  value 4.7k  [RES-0201]  (hidden comment: RC0201FR-074K7L)
R417  value 0  [RES-0201]  (hidden comment: CRCW02010000Z0ED)
R418  value 0  [RES-0201]  (hidden comment: CRCW02010000Z0ED)
R419  value 0  [RES-0201]  (hidden comment: CRCW02010000Z0ED)
TP87  Test point 1.00mm  [TP-1.00MM]  (value not drawn)  (no BOM)

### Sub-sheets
U_LOAD_SWITCH_5V = LOAD_SWITCH_5V.SchDoc: IN (in), OUT (out), ON (in), ILIM (in)

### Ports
I2C_1V8 (harness I2C), PCIE_4LANES (in, harness SOM_MD_PCIE1), POWER_EN (in)

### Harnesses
SOM_MD_PCIE1: RX0_N, RX0_P, TX0_P, TX0_N, RX1_N, RX1_P, TX1_P, TX1_N, REFCLK_N, REFCLK_P, RX2_N, RX2_P, TX2_P, TX2_N, RX3_N, RX3_P, TX3_P, TX3_N, WAKE_N, CLKREQ_N, RST_N
I2C: SDA, SCL

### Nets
GND: C224.1 C225.1 C226.1 C227.1 D27.1(A1) D28.3 D28.8 D29.3 D29.8 D30.3 D30.8 D31.3 D31.8 D32.3 D32.8 D33.1(A1) D34.1(A1) D35.1(A1) D40.1(A1) D41.1(A1) D42.1(A1) H5.1 J10.1(GND) J10.3(GND) J10.9(GND) J10.15(GND) J10.21(GND) J10.27(GND) J10.32(GND) J10.33(GND) J10.38(GND) J10.39(GND) J10.45(GND) J10.51(GND) J10.57(GND) J10.71(GND) J10.75(GND) J10.FIXING R179.1 R183.1
SOM_VREG_MDPX3_1P8: R224.1 R414.2 R415.2 R416.2
GPIO_21: R414.1 R417.2 ; port PCIE_4LANES.WAKE_N
GPIO_22: R415.1 R418.2 ; port PCIE_4LANES.CLKREQ_N
GPIO_23: R416.1 R419.2 ; port PCIE_4LANES.RST_N
MD_GPIO_29: R226.1 ; port I2C_1V8.SDA
MD_GPIO_30: R225.1 ; port I2C_1V8.SCL
MD_GPIO_51: R179.2 ; port POWER_EN, sheet U_LOAD_SWITCH_5V/ON
MD_PCIE1_4LANES.REFCLK_N: D32.1 D32.10 J10.53(REFCLKN) ; port PCIE_4LANES.REFCLK_N
MD_PCIE1_4LANES.REFCLK_P: D32.2 D32.9 J10.55(REFCLKP) ; port PCIE_4LANES.REFCLK_P
MD_PCIE1_4LANES.RX0_N: D31.1 D31.10 J10.41(PETn0) ; port PCIE_4LANES.RX0_N
MD_PCIE1_4LANES.RX0_P: D31.2 D31.9 J10.43(PETp0) ; port PCIE_4LANES.RX0_P
MD_PCIE1_4LANES.RX1_N: D30.1 D30.10 J10.29(PETn1) ; port PCIE_4LANES.RX1_N
MD_PCIE1_4LANES.RX1_P: D30.2 D30.9 J10.31(PETp1) ; port PCIE_4LANES.RX1_P
MD_PCIE1_4LANES.RX2_N: D29.1 D29.10 J10.17(PETn2) ; port PCIE_4LANES.RX2_N
MD_PCIE1_4LANES.RX2_P: D29.2 D29.9 J10.19(PETp2) ; port PCIE_4LANES.RX2_P
MD_PCIE1_4LANES.RX3_N: D28.1 D28.10 J10.5(PETn3) ; port PCIE_4LANES.RX3_N
MD_PCIE1_4LANES.RX3_P: D28.2 D28.9 J10.7(PETp3) ; port PCIE_4LANES.RX3_P
MD_PCIE1_4LANES.TX0_N: D31.4 D31.7 J10.47(PERn0) ; port PCIE_4LANES.TX0_N
MD_PCIE1_4LANES.TX0_P: D31.5 D31.6 J10.49(PERp0) ; port PCIE_4LANES.TX0_P
MD_PCIE1_4LANES.TX1_N: D30.4 D30.7 J10.35(PERn1) ; port PCIE_4LANES.TX1_N
MD_PCIE1_4LANES.TX1_P: D30.5 D30.6 J10.37(PERp1) ; port PCIE_4LANES.TX1_P
MD_PCIE1_4LANES.TX2_N: D29.4 D29.7 J10.23(PERn2) ; port PCIE_4LANES.TX2_N
MD_PCIE1_4LANES.TX2_P: D29.5 D29.6 J10.25(PERp2) ; port PCIE_4LANES.TX2_P
MD_PCIE1_4LANES.TX3_N: D28.4 D28.7 J10.11(PERn3) ; port PCIE_4LANES.TX3_N
MD_PCIE1_4LANES.TX3_P: D28.5 D28.6 J10.13(PERp3) ; port PCIE_4LANES.TX3_P
NetC224_2: C224.2 C225.2 C226.2 C227.2 D27.2(A2) D40.2(A2) J10.2(3.3V) J10.4(3.3V) J10.12(3.3V) J10.14(3.3V) J10.16(3.3V) J10.18(3.3V) J10.70(3.3V) J10.72(3.3V) J10.74(3.3V) TP87.X ; sheet U_LOAD_SWITCH_5V/OUT
NetD32_4: D32.4 D32.7
NetD32_5: D32.5 D32.6
NetD33_2: D33.2(A2) J10.54(PEWAKE#_(I/O)(0/1.8V/3.3V)) R417.1
NetD34_2: D34.2(A2) J10.52(CLKREQ#_(I/O)(0/1.8V/3.3V)) R418.1
NetD35_2: D35.2(A2) J10.50(PERST#_(I)(0/1.8V/3.3V)) R419.1
NetD41_2: D41.2(A2) J10.40(SMB_CLK(I/O)(0/1.8V)) R225.2
NetD42_2: D42.2(A2) J10.42(SMB_DATA(I/O)(0/1.8V)) R226.2
NetJ10_22: J10.22(VIO_1.8V) R224.2
NetR183_2: R183.2 ; sheet U_LOAD_SWITCH_5V/ILIM

Not connected (* = marked no-connect by the designer): J10 6(PWRDIS(I)(0/1.8/3.3V))* 8(PLN#(I)(0/1.8/3.3V))* 10(LED_1#(O)(OD)) 20(N/C)* 24(N/C)* 26(N/C)* 28(N/C)* 30(PLA_S3#(O)(0/1.8/3.3V))* 34(USB_D+)* 36(USB_D-)* 44(ALERT#(O)(0/1.8V))* 46(N/C)* 48(N/C)* 56(Reserved_for_MFG_DATA)* 58(Reserved_for_MFG_CLOCK)* 67(N/C)* 68(SUSCLK(I)(0/1.8V/3.3V))* 69(PEDET_(NC-PCIe))* 73(VIO_CFG_(O))

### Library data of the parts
C224 C225 = C0113-A.6: as C305 on sheet HEATSINK_FAN
C226 C227 = C0199-A.1: CAP CHIP 0805 47uF 20% 6.3V X5R; Manufacturer: KEMET; Code Arduino: C0199
D27 D33-D35 D40-D42 = D0099-5: as D83-D89 on sheet HEADERS_JMEDIA_JMISC
D28-D32 = D0097-A.6: as D90-D97 on sheet HEADERS_JMEDIA_JMISC
H5 = S0074-A.2: M2 SPACER SMT ROUND STEEL H=4mm; Manufacturer: Wurth Elektronik; Code Arduino: S0074
J10 = J0573-A.2: CONN PCIE-based M.2 NGFF, KEY M, heigth 5.8mm board heigth 4.14mm gold plated, TOP MOUNT; Manufacturer: Amphenol; Code Arduino: J0573
R179 = R0145-A.21: as R317 on sheet HEADERS_JCTL
R183 = R0399-A.1: RES CHIP 0201 18k 1% 1/20W; Manufacturer: YAGEO; Power: 50mW; Code Arduino: R0399; Temperature Coefficient: 200ppm
R224-R226 R417-R419 = R0140-A.21: as R508 on sheet HEADERS_JMEDIA_JMISC
R414-R416 = R0151-A.21: RES CHIP 0201 4k7 1% 1/20W; Manufacturer: Yageo; Temperature coefficient: 200ppm; Power: 50mW; Code Arduino: A5521
TP87 = UT0013-A.6: Part Number: This is not a component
